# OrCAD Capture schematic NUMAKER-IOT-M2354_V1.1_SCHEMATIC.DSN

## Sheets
1 Nu-Link2-Me: size A3; title: Nu-Link2-Me; rev: 1.0; company: CMHuang; note: Nu-Link2-Me
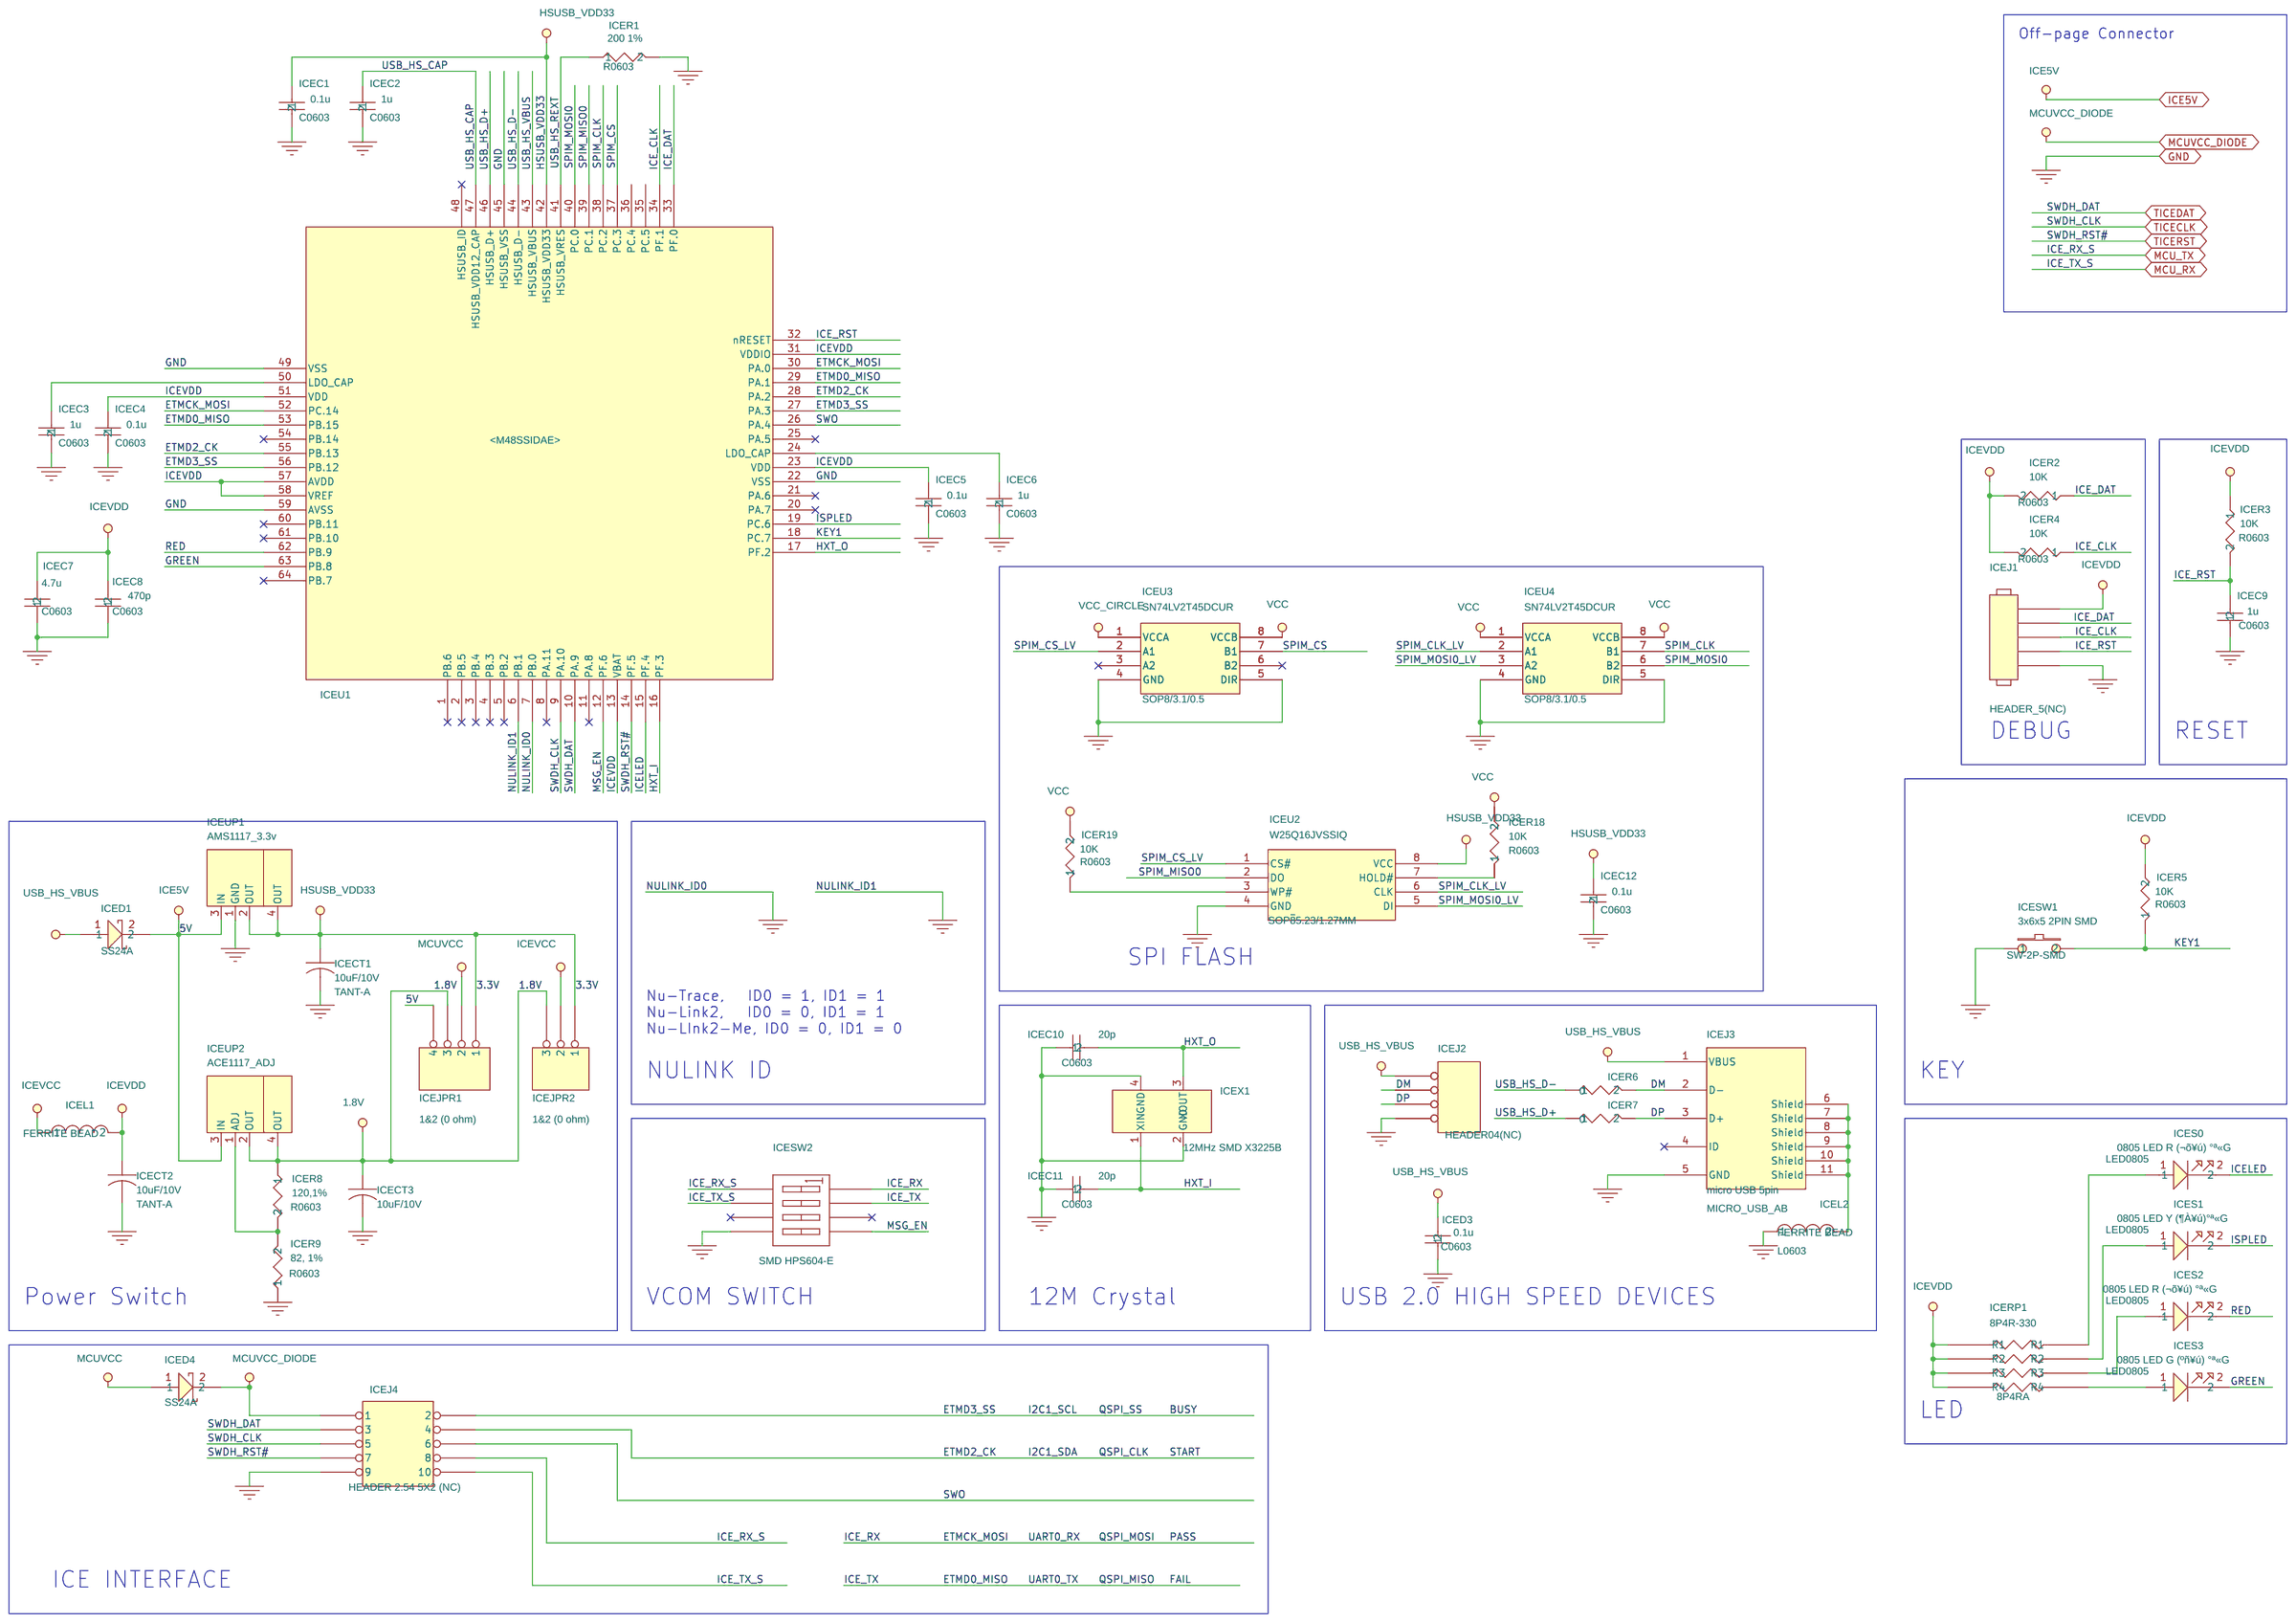
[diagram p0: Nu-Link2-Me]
2 M2354KJFAE: size Custom; title: M2354KJFAE; rev: v1.1; note: NuMaker-IoT-M2354
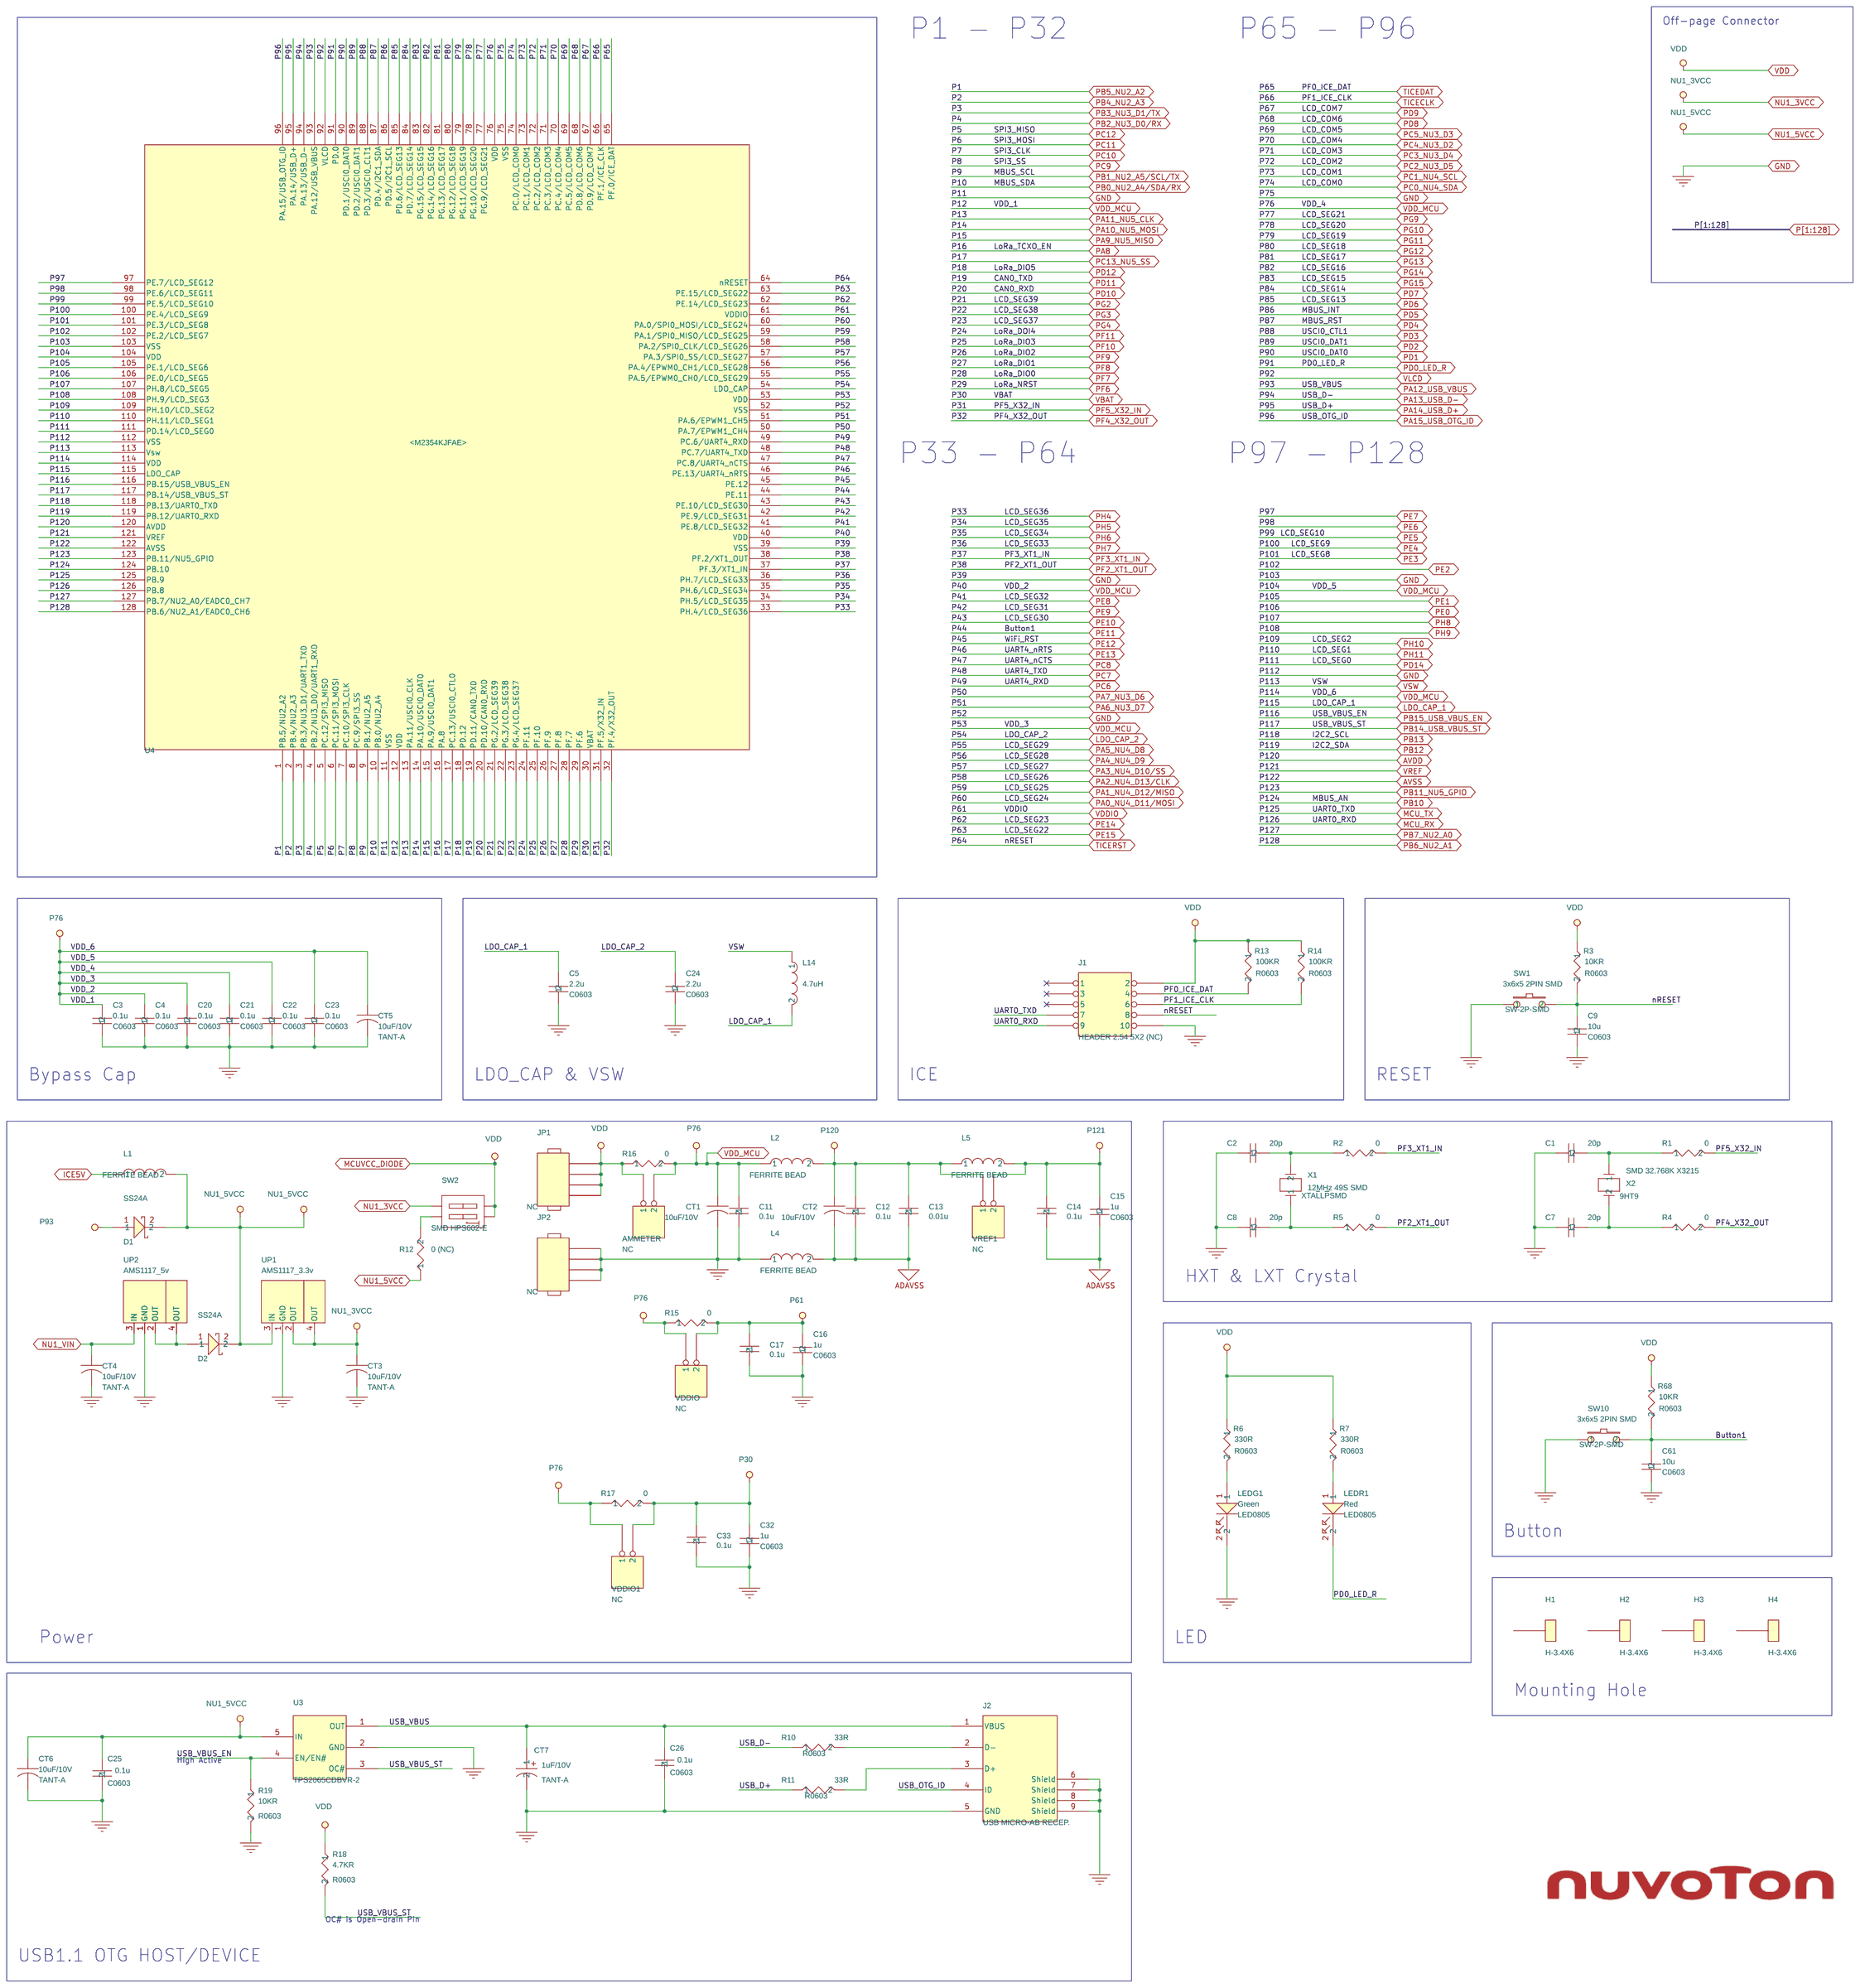
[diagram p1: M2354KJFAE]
3 Ext. Connector: size Custom; title: UNO Interface; rev: v1.1; note: NuMaker-IoT-M2354
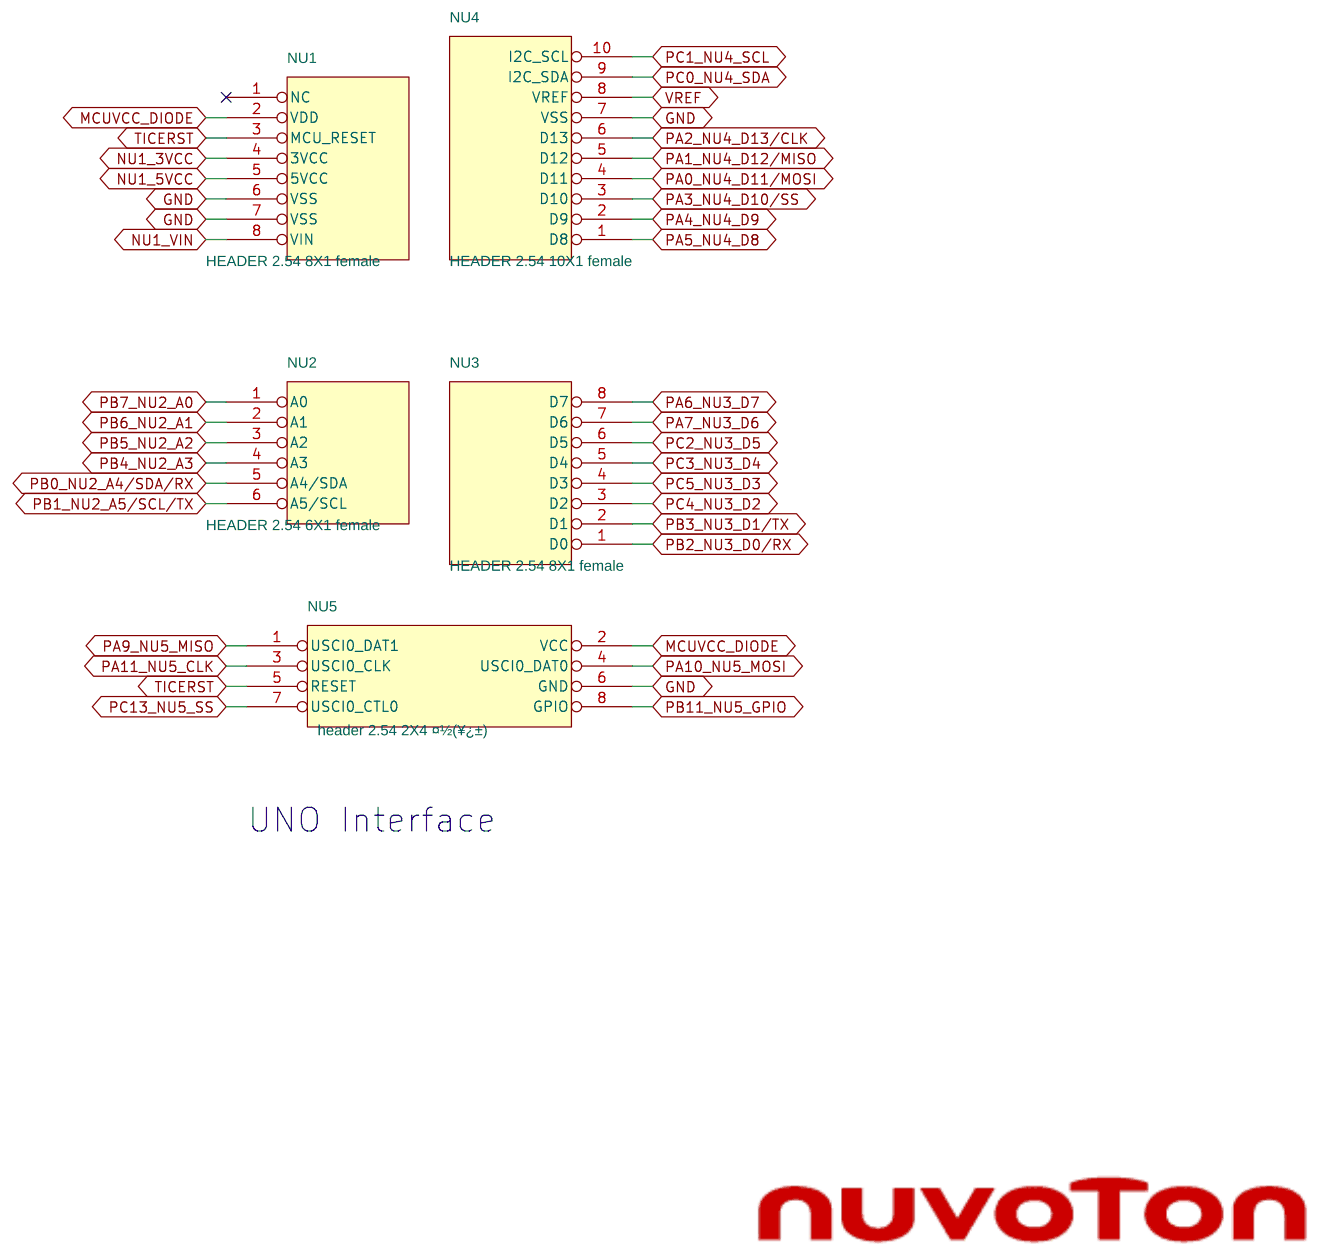
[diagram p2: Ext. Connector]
4 WiFi: size A; title: WiFi; rev: v1.1; note: NuMaker-IoT-M2354
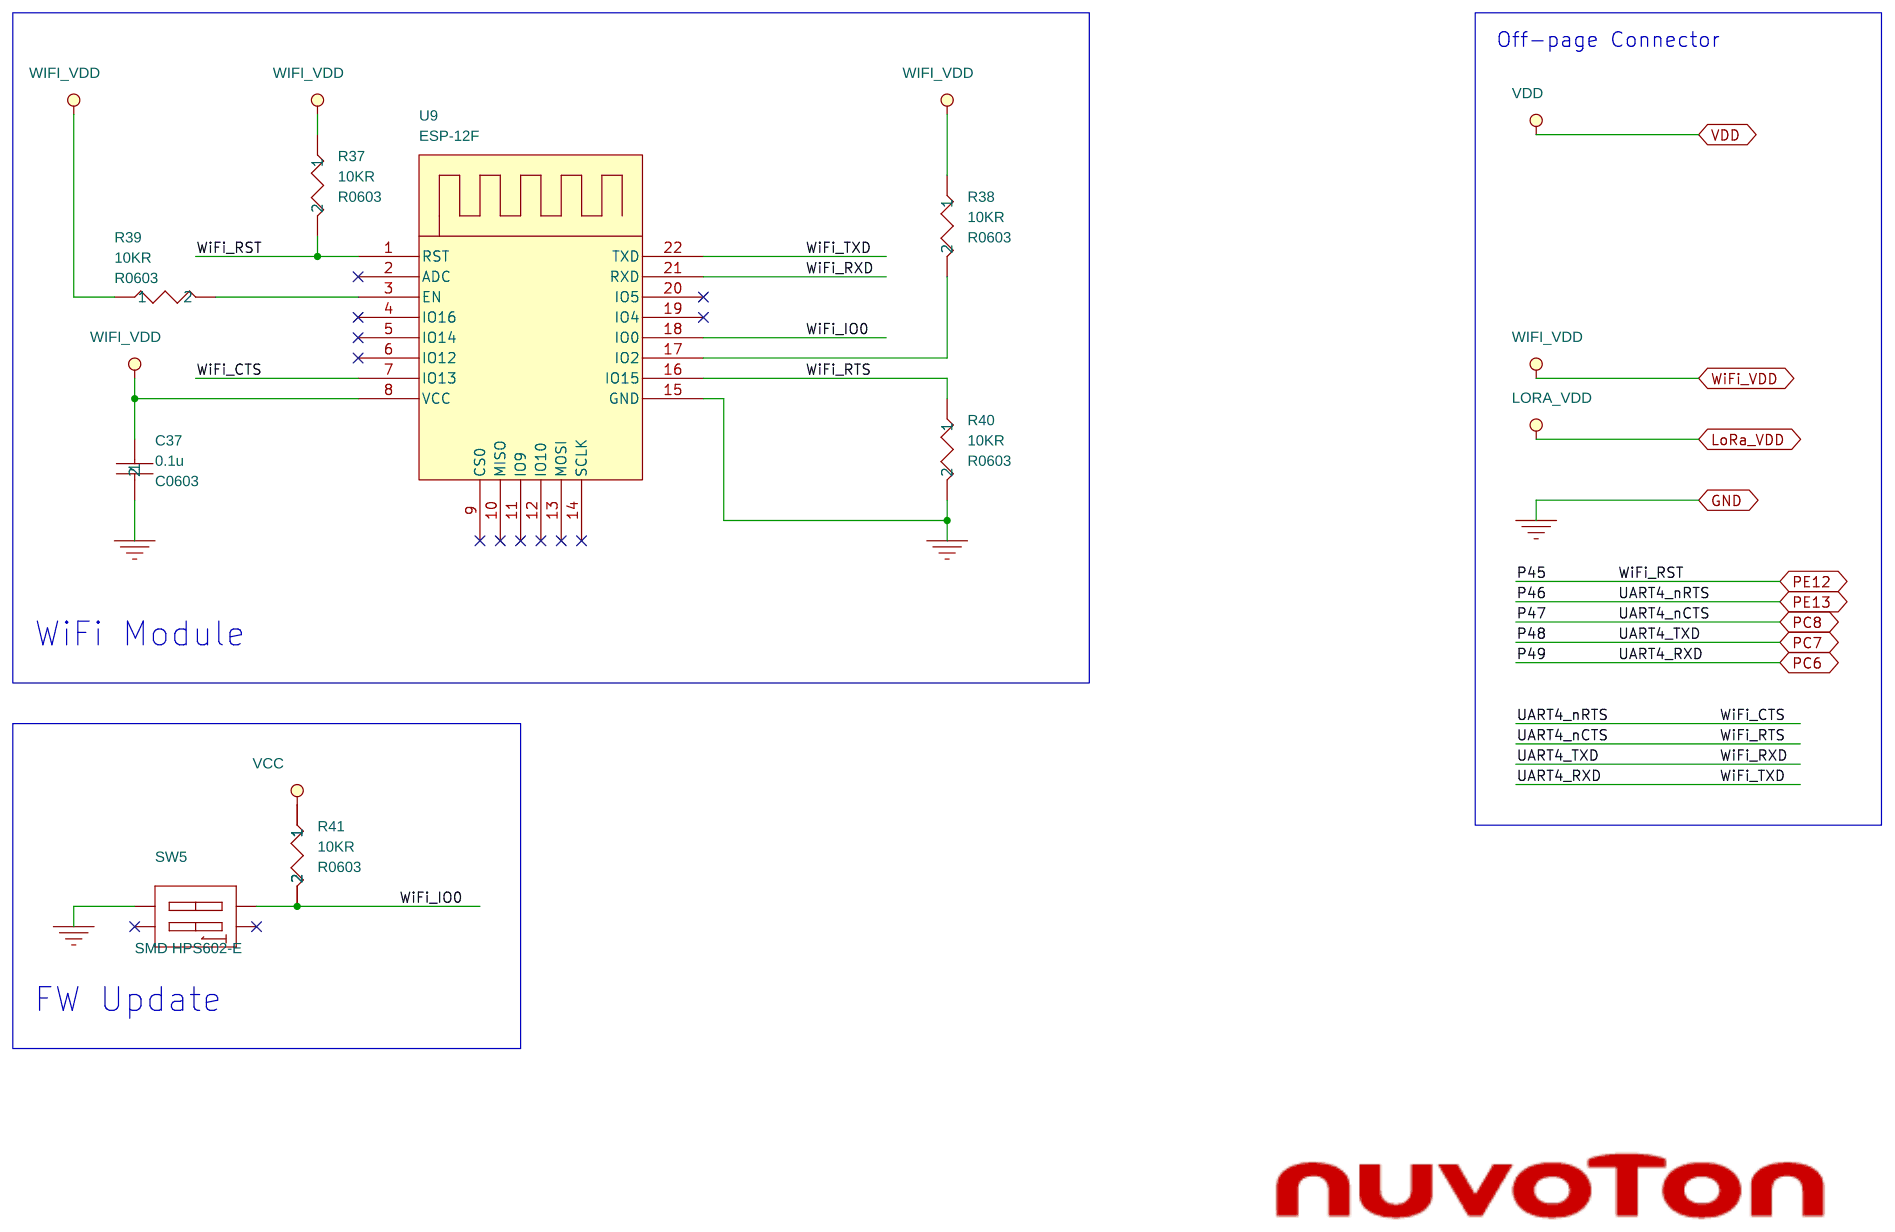
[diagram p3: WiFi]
5 LoRa: size Custom; title: LoRa; rev: v1.1; note: NuMaker-IoT-M2354
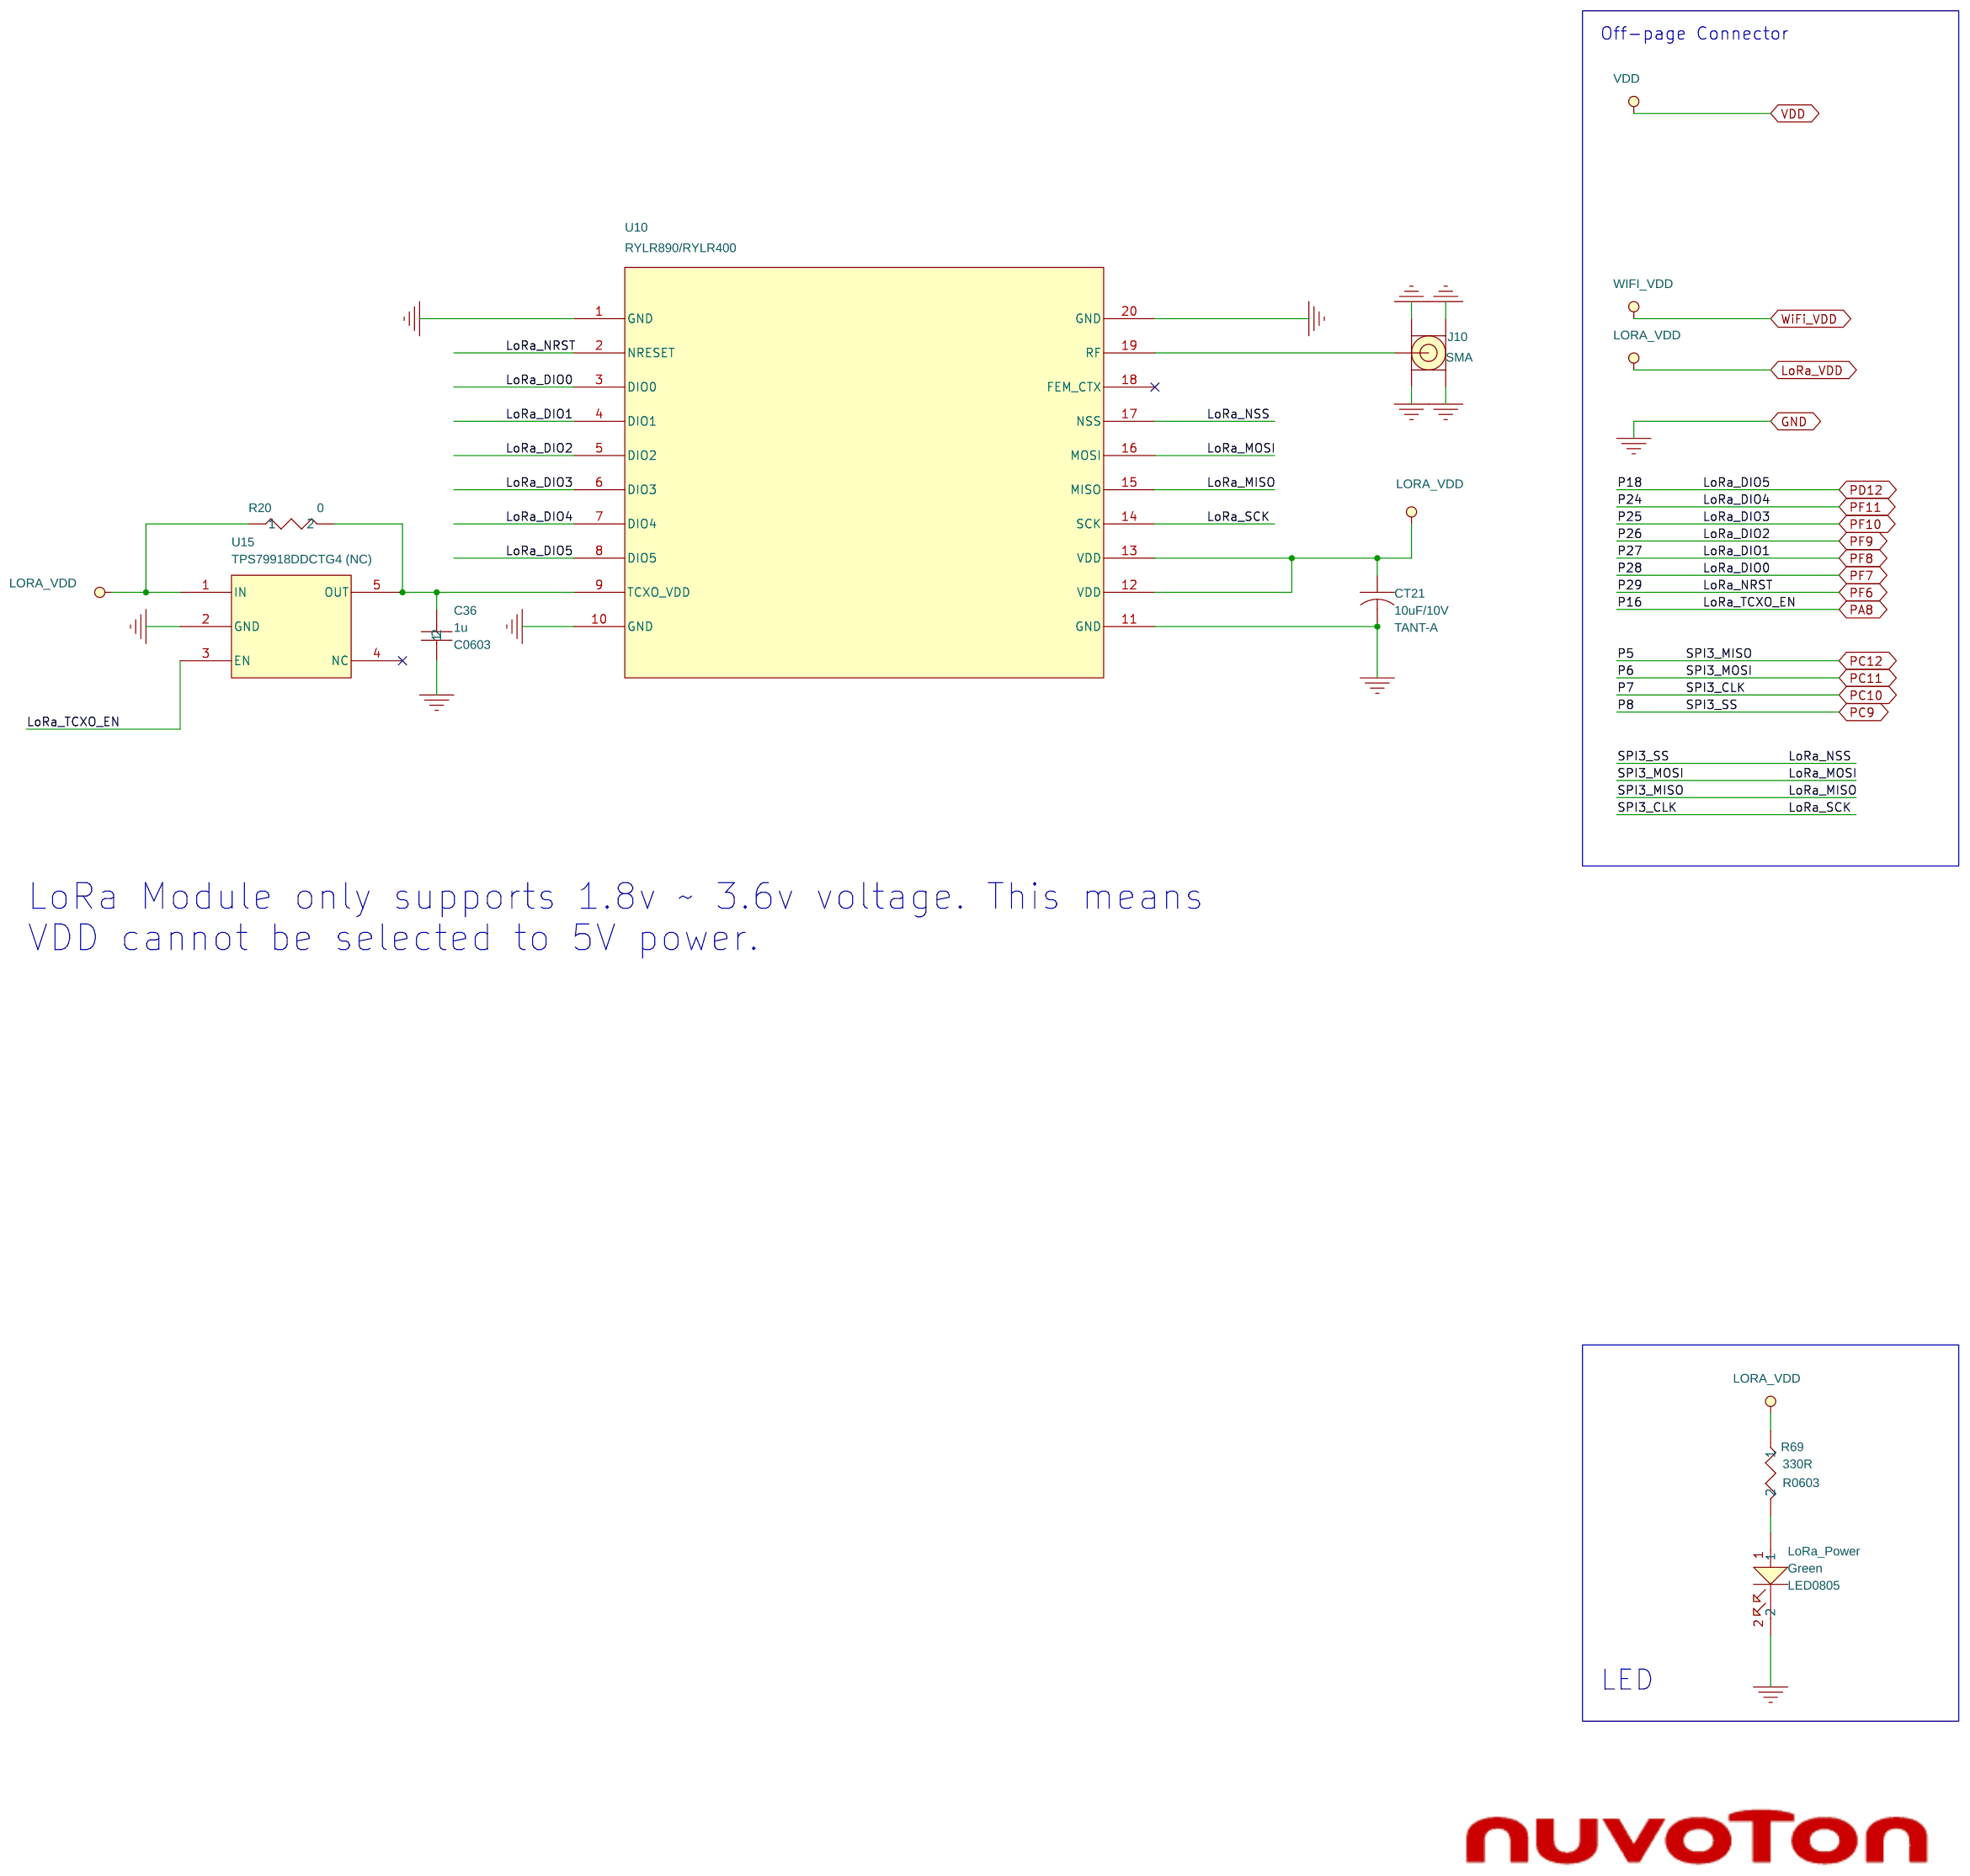
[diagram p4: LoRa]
6 Sensor: size A; title: Sensor; rev: v1.1; note: NuMaker-IoT-M2354
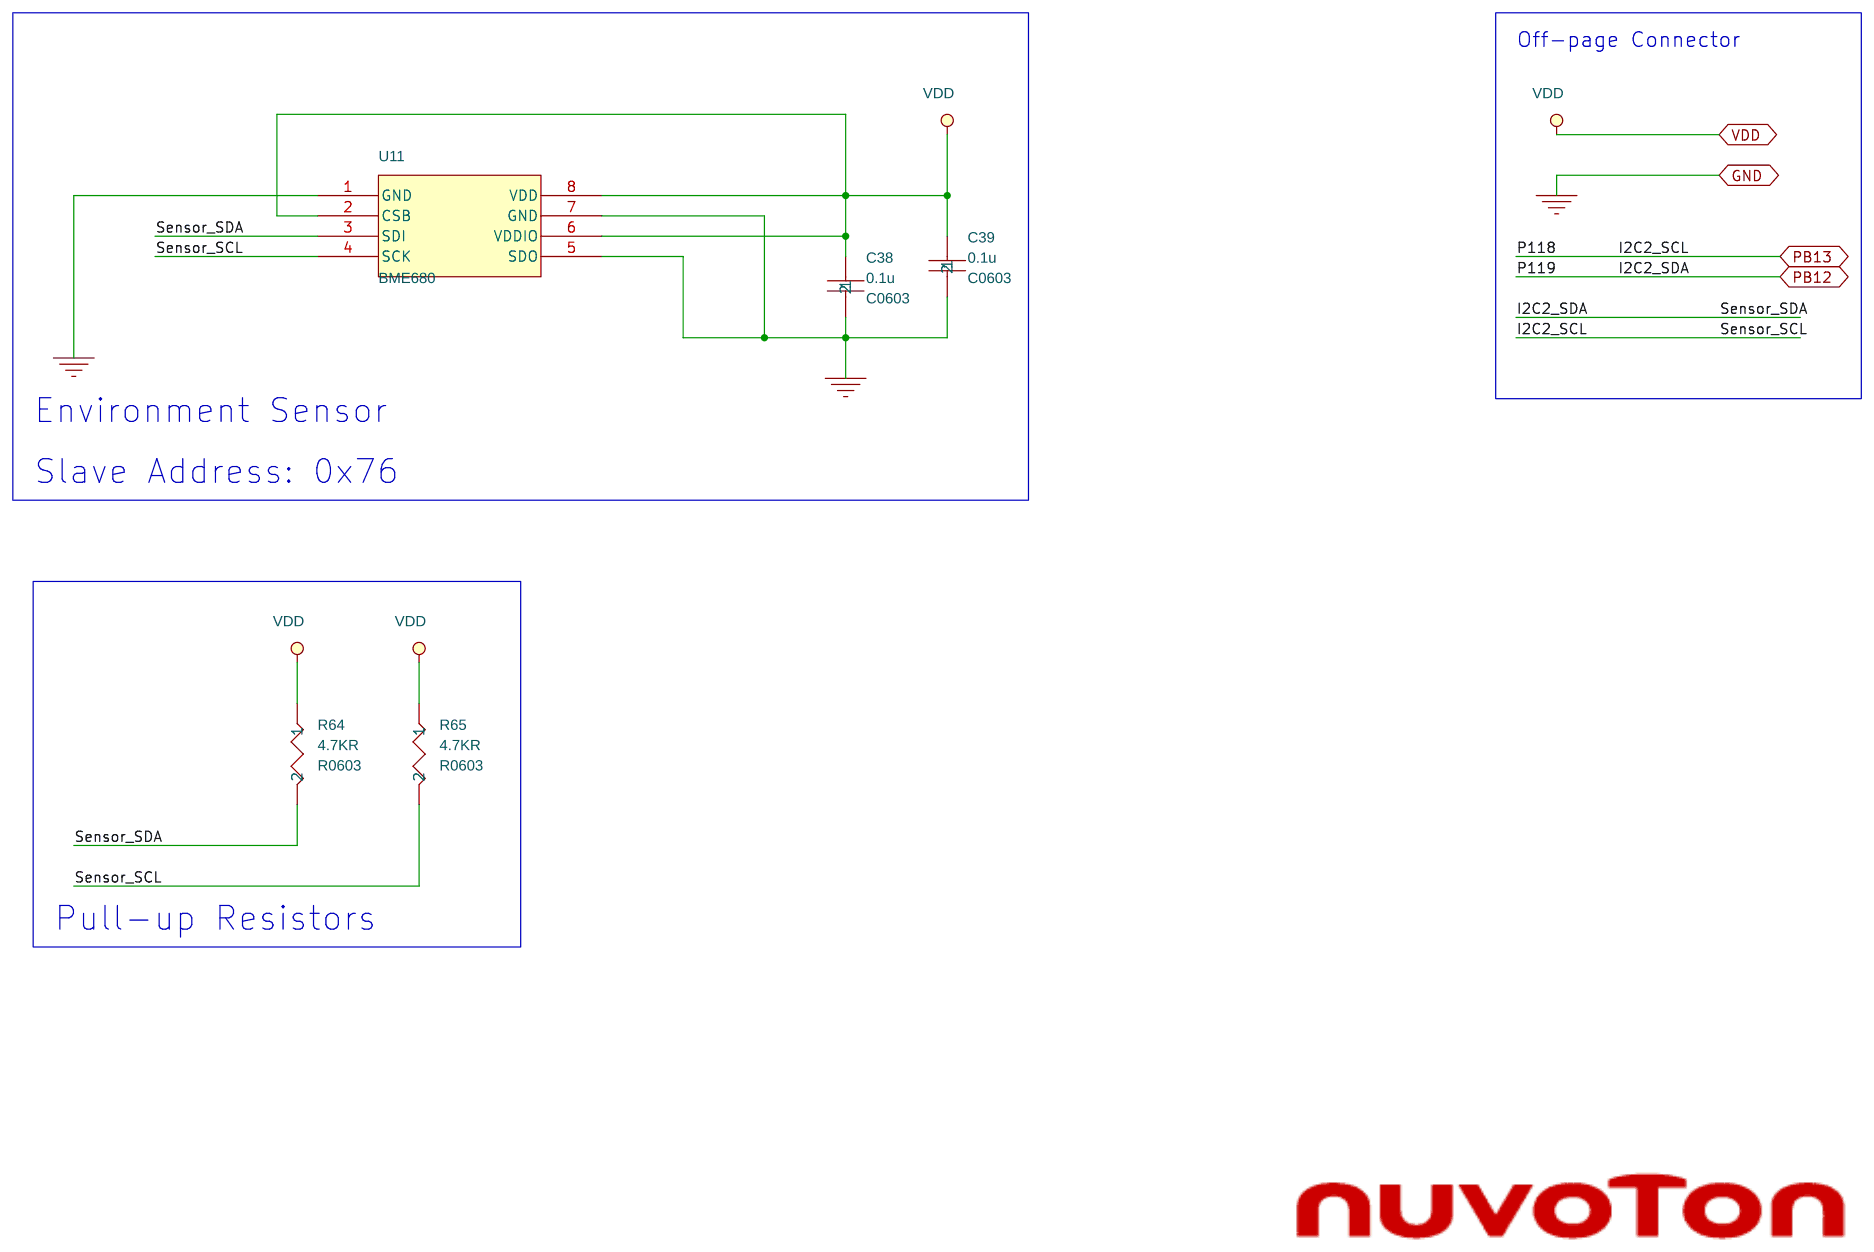
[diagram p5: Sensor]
7 CAN & RS485: size Custom; title: CAN & RS485; rev: v1.1; note: NuMaker-IoT-M2354
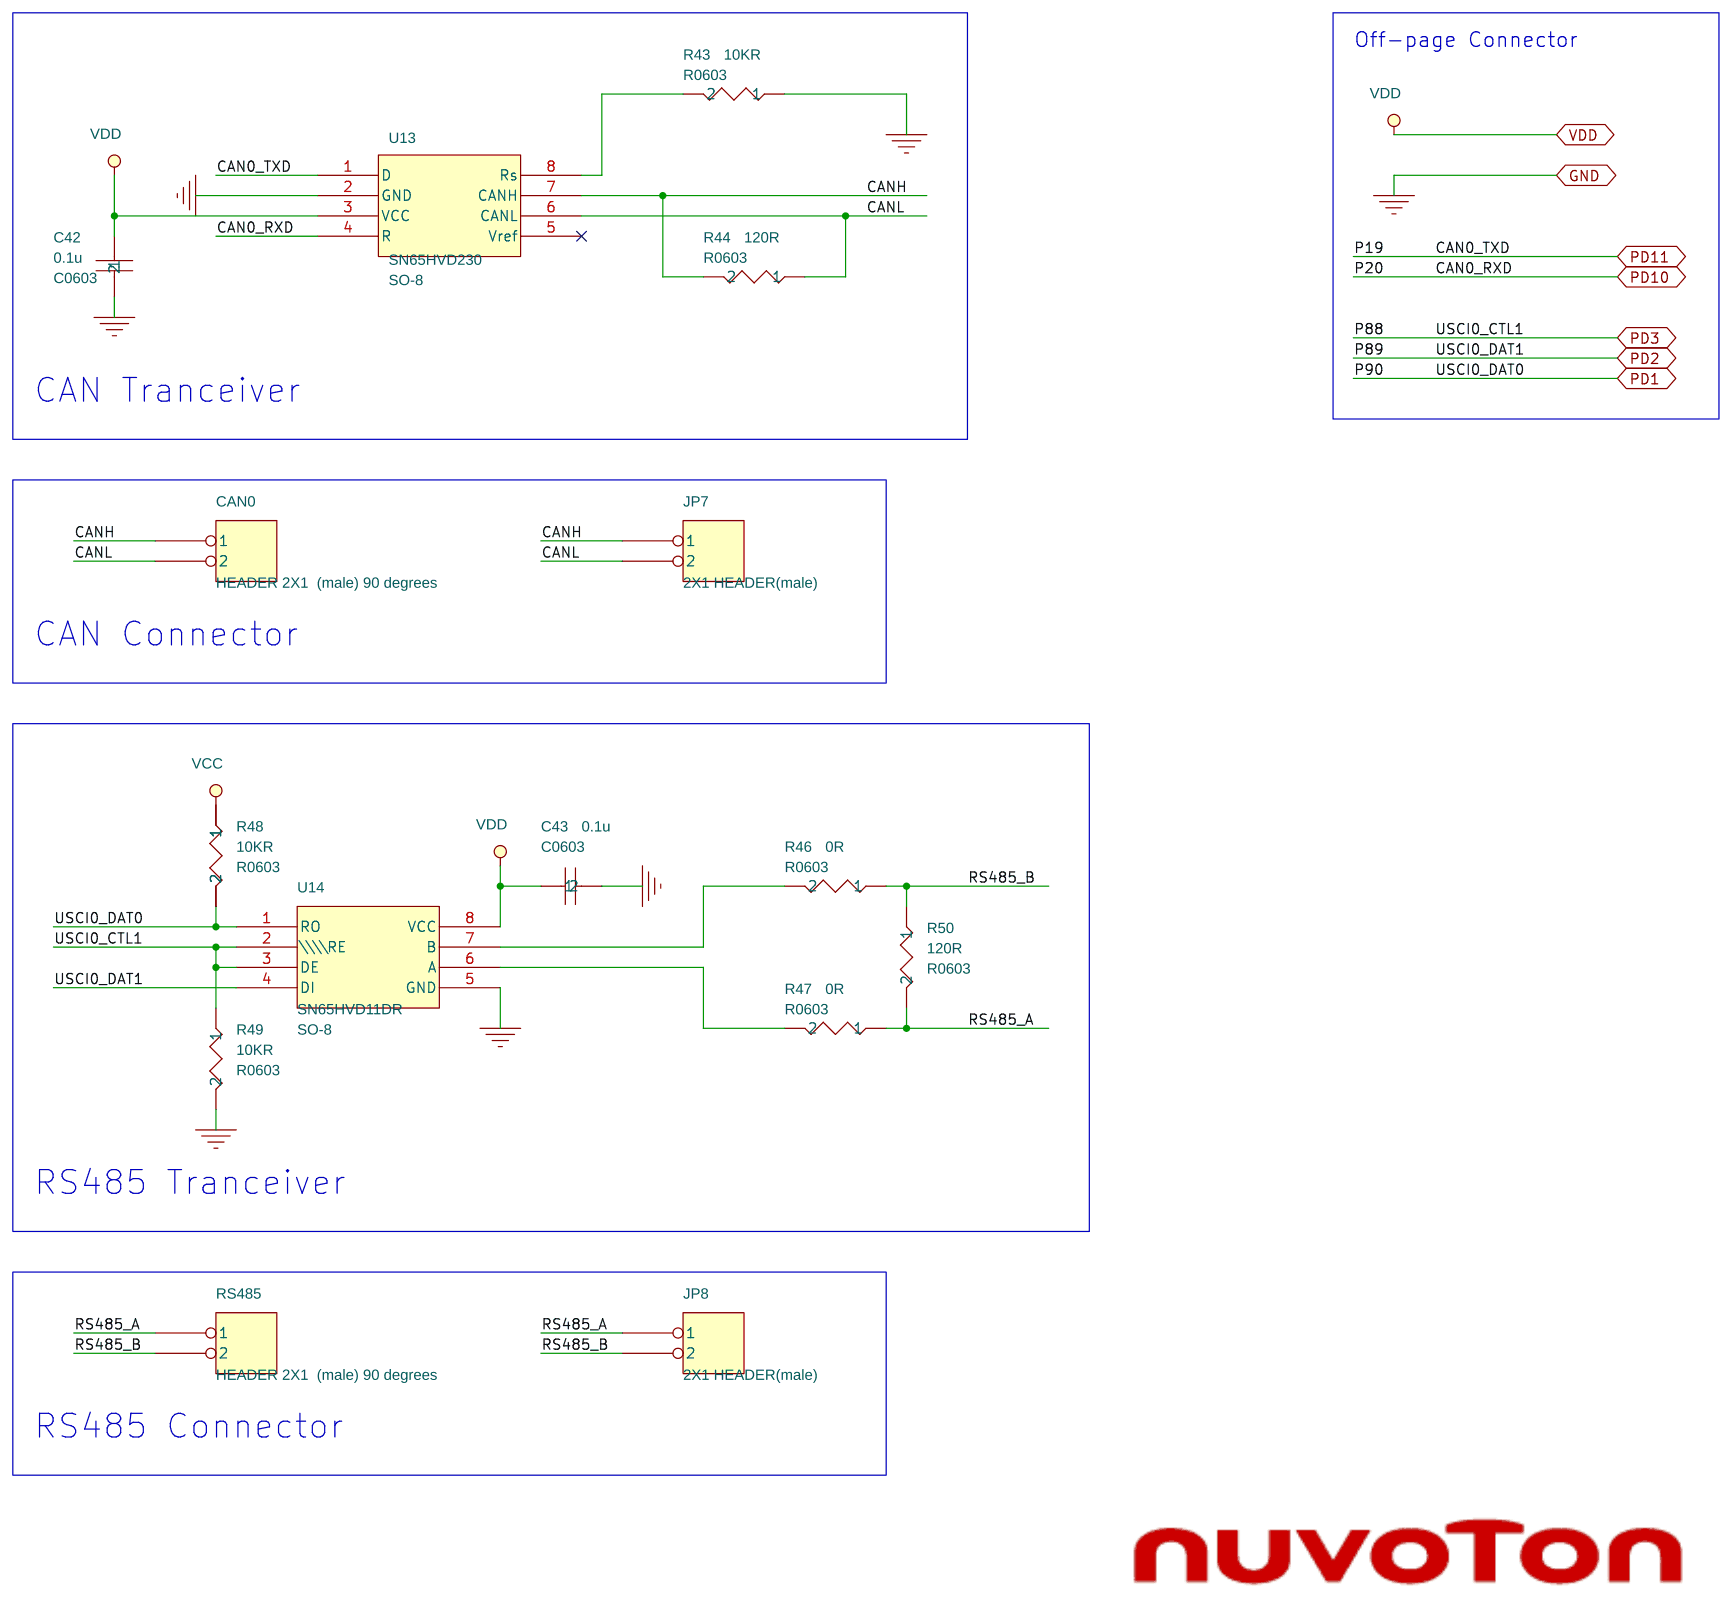
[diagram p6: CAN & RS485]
8 MikroBUS: size A; title: MikroBUS interface; rev: 1.1; note: NuMaker-IoT-M2354
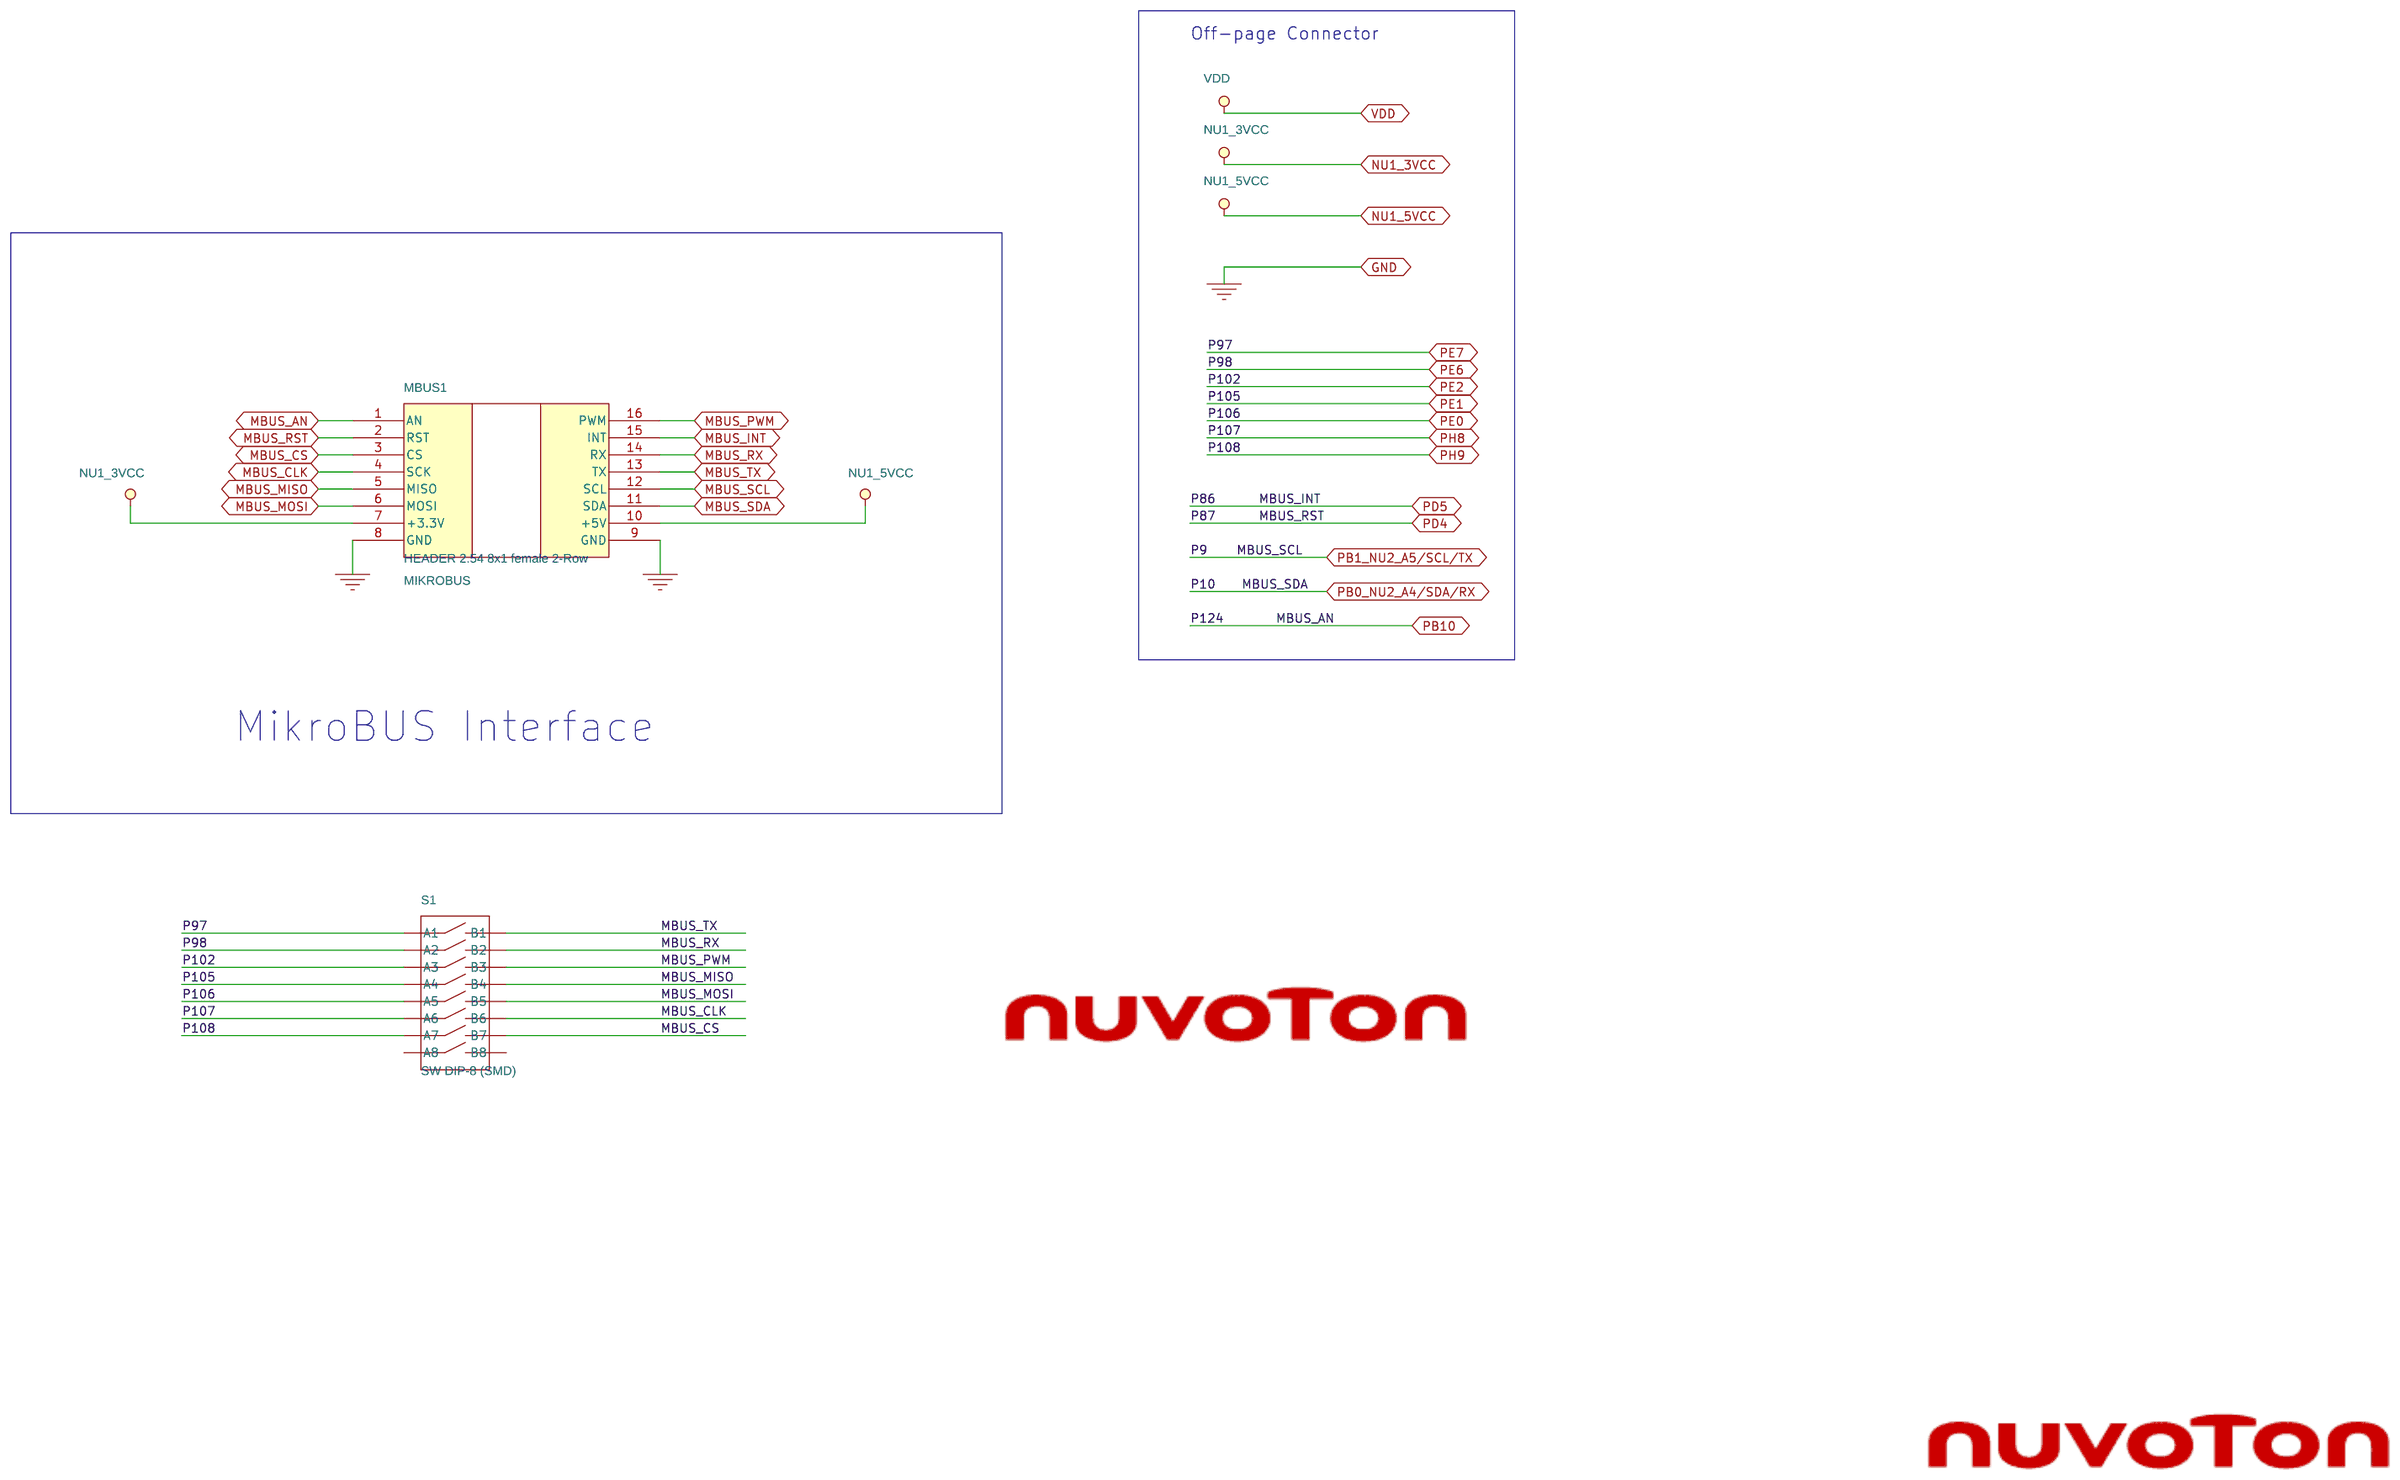
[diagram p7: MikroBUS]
9 LCD: size A; title: LCD interface; rev: V1.1; note: NuMaker-IoT-M2354
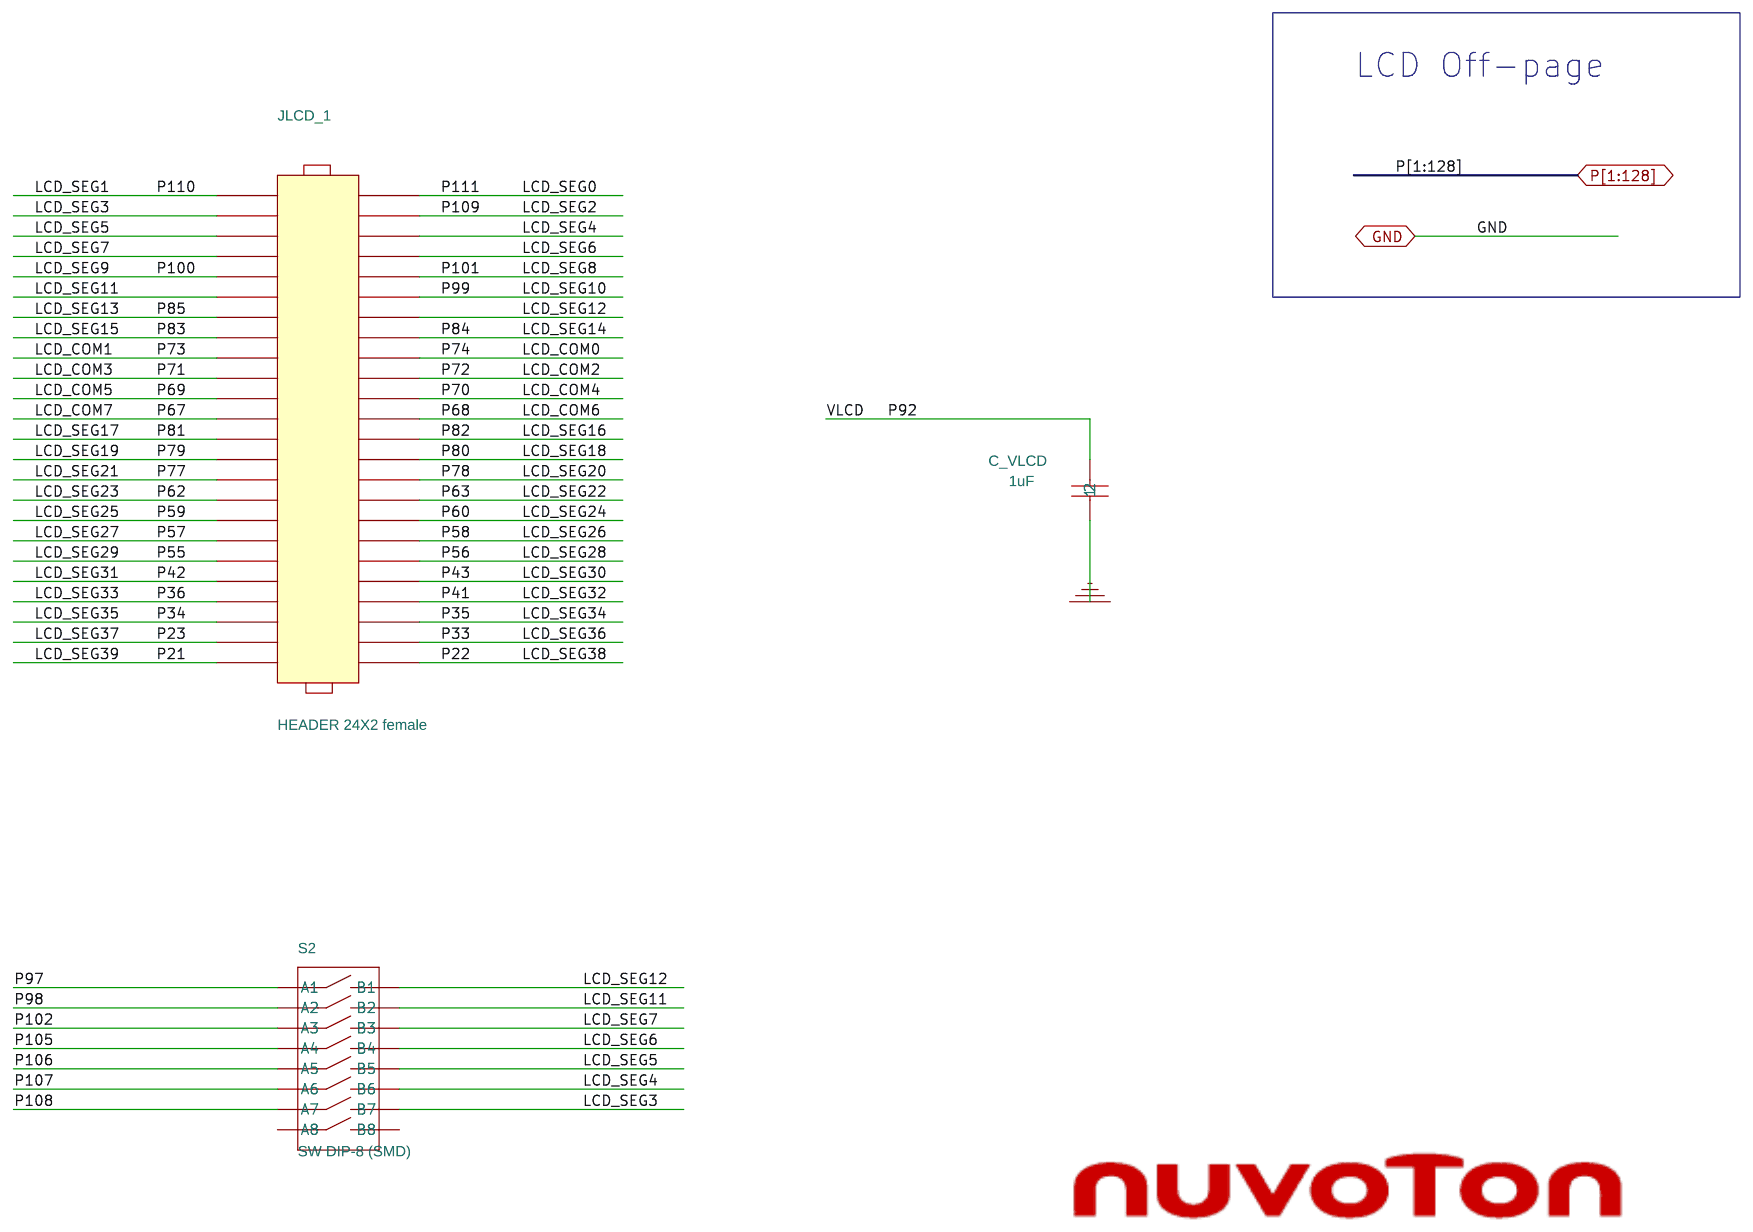
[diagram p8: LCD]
10 Module Power: size Custom; title: Module Power; rev: v1.1; note: NuMaker-IoT-M2354
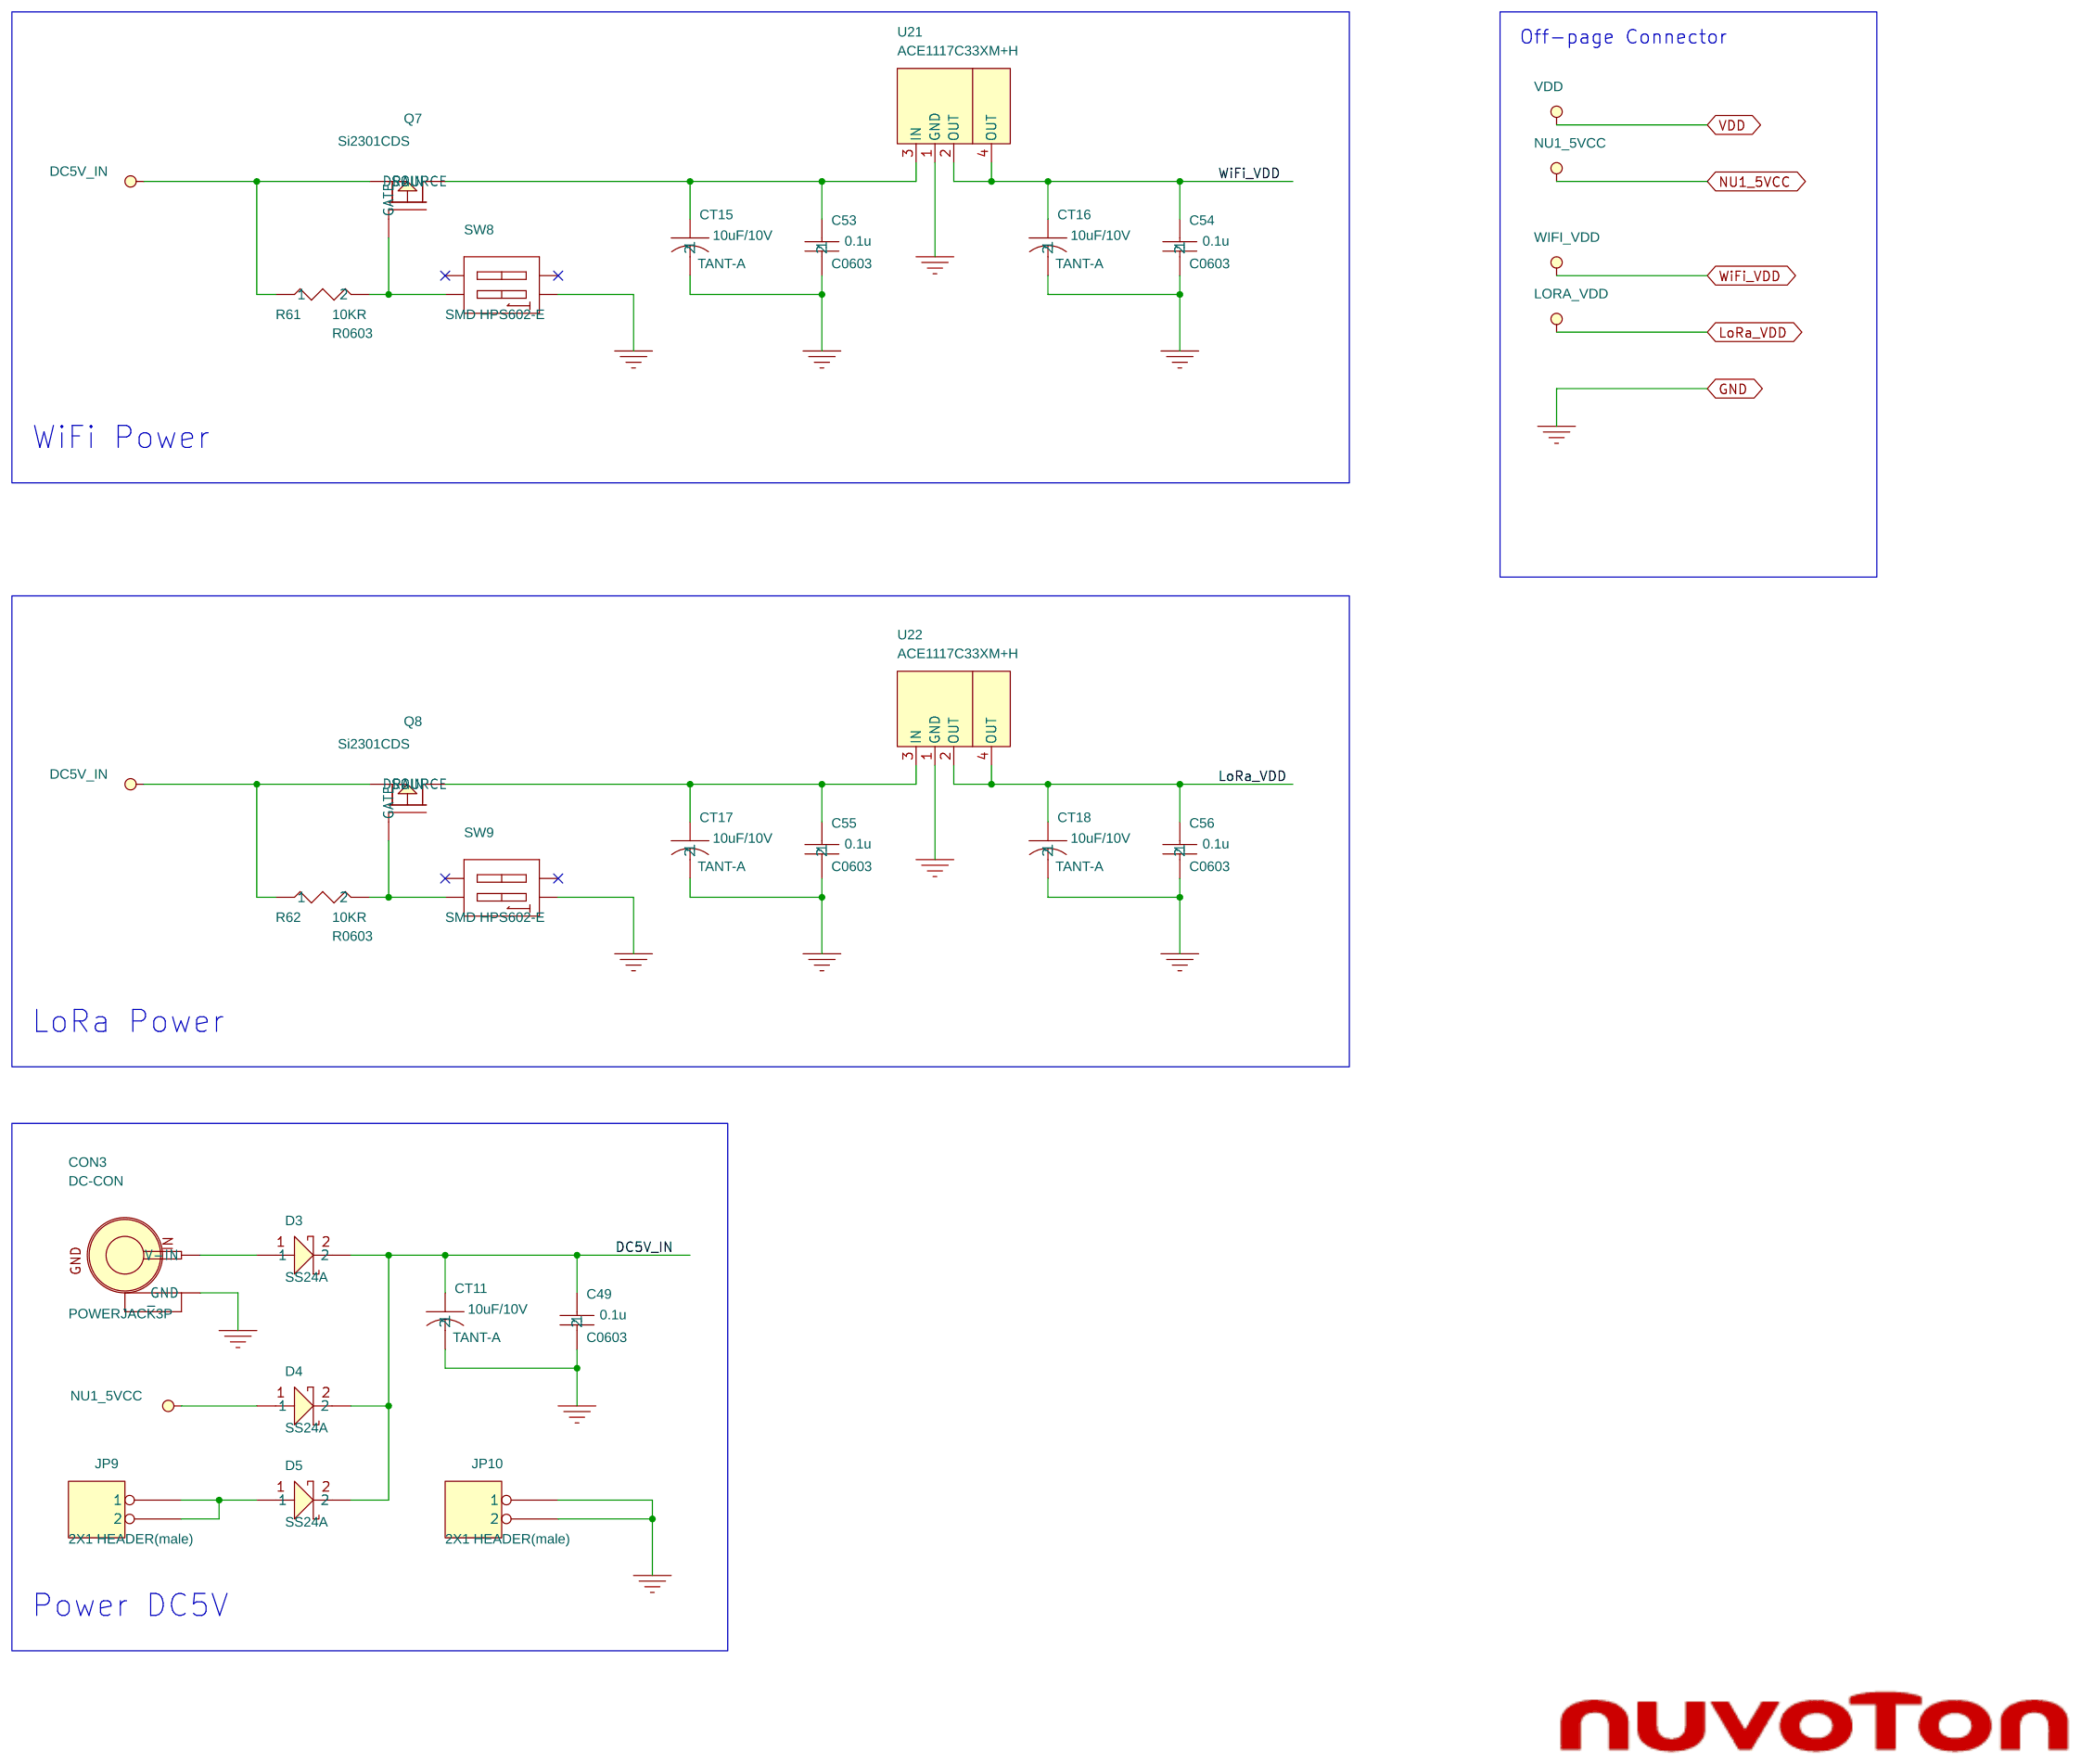
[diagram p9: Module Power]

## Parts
sheet CAN & RS485
C42  0.1u  [C0603]
C43  0.1u  [C0603]
CAN0  HEADER 2X1  (male) 90 degrees  [SIP/2P_3.5MM]
JP7  2X1 HEADER(male)  [HEADER2X1]
JP8  2X1 HEADER(male)  [HEADER2X1]
R43  10KR  [R0603]
R44  120R  [R0603]
R46  0R  [R0603]
R47  0R  [R0603]
R48  10KR  [R0603]
R49  10KR  [R0603]
R50  120R  [R0603]
RS485  HEADER 2X1  (male) 90 degrees  [SIP/2P_3.5MM]
U13  SN65HVD230  [SO-8]
U14  SN65HVD11DR  [SO-8]
sheet Ext. Connector
NU1  HEADER 2.54 8X1 female  [SIP-8P]
NU2  HEADER 2.54 6X1 female  [SIP-6P]
NU3  HEADER 2.54 8X1 female  [SIP-8P]
NU4  HEADER 2.54 10X1 female  [SIP-10P]
NU5  header 2.54 2X4 ¤½(¥¿­±)  [HEADER4X2]
sheet LCD
C_VLCD  1uF  [C0603]
JLCD_1  HEADER 24X2 female  [HEADER24X2_2mm]
S2  SW DIP-8 (SMD)  [SW_DIP-8_(SMD)]
sheet LoRa
C36  1u  [C0603]
CT21  10uF/10V  [TANT-A]
J10  SMA  [SMA_5PIN]
LoRa_Power  Green  [LED0805]
R20  0  [R0603]
R69  330R  [R0603]
U10  RYLR890/RYLR400  [RYLR_LORA]
U15  TPS79918DDCTG4 (NC)  [SOT23-5]
sheet M2354KJFAE
AMMETER  NC  [HEADER2X1]
C1  20p  [C0603]
C2  20p  [C0603]
C3  0.1u  [C0603]
C4  0.1u  [C0603]
C5  2.2u  [C0603]
C7  20p  [C0603]
C8  20p  [C0603]
C9  10u  [C0603]
C11  0.1u  [C0603]
C12  0.1u  [C0603]
C13  0.01u  [C0603]
C14  0.1u  [C0603]
C15  1u  [C0603]
C16  1u  [C0603]
C17  0.1u  [C0603]
C20  0.1u  [C0603]
C21  0.1u  [C0603]
C22  0.1u  [C0603]
C23  0.1u  [C0603]
C24  2.2u  [C0603]
C25  0.1u  [C0603]
C26  0.1u  [C0603]
C32  1u  [C0603]
C33  0.1u  [C0603]
C61  10u  [C0603]
CT1  10uF/10V  [TANT-A]
CT2  10uF/10V  [TANT-A]
CT3  10uF/10V  [TANT-A]
CT4  10uF/10V  [TANT-A]
CT5  10uF/10V  [TANT-A]
CT6  10uF/10V  [TANT-A]
CT7  1uF/10V  [TANT-A]
D1  SS24A  [RB060L]
D2  SS24A  [RB060L]
H1  H-3.4X6  [H-3.4X6]
H2  H-3.4X6  [H-3.4X6]
H3  H-3.4X6  [H-3.4X6]
H4  H-3.4X6  [H-3.4X6]
J1  HEADER 2.54 5X2 (NC)  [HEADER5X2]
J2  USB MICRO-AB RECEP.  [MICRO_USB_AB_LS]
JP1  NC  [header1x4]
JP2  NC  [header1x4]
L1  FERRITE BEAD  [L0603]
L2  FERRITE BEAD  [L0603]
L4  FERRITE BEAD  [L0603]
L5  FERRITE BEAD  [L0603]
L14  4.7uH  [L-VLF403215MT]
LEDG1  Green  [LED0805]
LEDR1  Red  [LED0805]
R1  0  [R0603]
R2  0  [R0603]
R3  10KR  [R0603]
R4  0  [R0603]
R5  0  [R0603]
R6  330R  [R0603]
R7  330R  [R0603]
R10  33R  [R0603]
R11  33R  [R0603]
R12  0 (NC)  [R0603]
R13  100KR  [R0603]
R14  100KR  [R0603]
R15  0  [R0603]
R16  0  [R0603]
R17  0  [R0603]
R18  4.7KR  [R0603]
R19  10KR  [R0603]
R68  10KR  [R0603]
SW1  3x6x5 2PIN SMD  [SW-2P-SMD]
SW2  SMD HPS602-E  [SW1X2]
SW10  3x6x5 2PIN SMD  [SW-2P-SMD]
U3  TPS2065CDBVR-2  [SOT23-5]
U4  M2354KJFAE  [MCU_LQFP_128]
UP1  AMS1117_3.3v  [SOT-223-1]
UP2  AMS1117_5v  [SOT-223-1]
VDDIO  NC  [HEADER2X1]
VDDIO1  NC  [HEADER2X1]
VREF1  NC  [HEADER2X1]
X1  12MHz 49S SMD  [XTAL\LP\SMD]
X2  SMD 32.768K X3215  [9HT9]
sheet MikroBUS
MBUS1  HEADER 2.54 8x1 female 2-Row  [MIKROBUS]
S1  SW DIP-8 (SMD)  [SW_DIP-8_(SMD)]
sheet Module Power
C49  0.1u  [C0603]
C53  0.1u  [C0603]
C54  0.1u  [C0603]
C55  0.1u  [C0603]
C56  0.1u  [C0603]
CON3  DC-CON  [POWERJACK\3P]
CT11  10uF/10V  [TANT-A]
CT15  10uF/10V  [TANT-A]
CT16  10uF/10V  [TANT-A]
CT17  10uF/10V  [TANT-A]
CT18  10uF/10V  [TANT-A]
D3  SS24A  [RB060L]
D4  SS24A  [RB060L]
D5  SS24A  [RB060L]
JP9  2X1 HEADER(male)  [HEADER2X1]
JP10  2X1 HEADER(male)  [HEADER2X1]
Q7  Si2301CDS  [SOT-23]
Q8  Si2301CDS  [SOT-23]
R61  10KR  [R0603]
R62  10KR  [R0603]
SW8  SMD HPS602-E  [SW1X2]
SW9  SMD HPS602-E  [SW1X2]
U21  ACE1117C33XM+H  [SOT-223-1]
U22  ACE1117C33XM+H  [SOT-223-1]
sheet Nu-Link2-Me
ICEC1  0.1u  [C0603]
ICEC2  1u  [C0603]
ICEC3  1u  [C0603]
ICEC4  0.1u  [C0603]
ICEC5  0.1u  [C0603]
ICEC6  1u  [C0603]
ICEC7  4.7u  [C0603]
ICEC8  470p  [C0603]
ICEC9  1u  [C0603]
ICEC10  20p  [C0603]
ICEC11  20p  [C0603]
ICEC12  0.1u  [C0603]
ICECT1  10uF/10V  [TANT-A]
ICECT2  10uF/10V  [TANT-A]
ICECT3  10uF/10V  [TANT-A]
ICED1  SS24A  [RB060L]
ICED3  0.1u  [C0603]
ICED4  SS24A  [RB060L]
ICEJ1  HEADER_5(NC)  [HEADER5X1]
ICEJ2  HEADER04(NC)  [HEADER04]
ICEJ3  micro USB 5pin  [MICRO_USB_AB]
ICEJ4  HEADER 2.54 5X2 (NC)  [HEADER5X2]
ICEJPR1  1&2 (0 ohm)  [R0603X3]
ICEJPR2  1&2 (0 ohm)  [R0603X2]
ICEL1  FERRITE BEAD  [L0603]
ICEL2  FERRITE BEAD  [L0603]
ICER1  200 1%  [R0603]
ICER2  10K  [R0603]
ICER3  10K  [R0603]
ICER4  10K  [R0603]
ICER5  10K  [R0603]
ICER6  0  [R0603]
ICER7  0  [R0603]
ICER8  120,1%  [R0603]
ICER9  82, 1%  [R0603]
ICER18  10K  [R0603]
ICER19  10K  [R0603]
ICERP1  8P4R-330  [8P4RA]
ICES0  0805 LED R (¬õ¥ú) °ª«G  [LED0805]
ICES1  0805 LED Y (¶À¥ú)°ª«G  [LED0805]
ICES2  0805 LED R (¬õ¥ú) °ª«G  [LED0805]
ICES3  0805 LED G (ºñ¥ú) °ª«G  [LED0805]
ICESW1  3x6x5 2PIN SMD  [SW-2P-SMD]
ICESW2  SMD HPS604-E  [SW1X4]
ICEU1  M48SSIDAE  [LQFP64_7x7_M48SSIDAE]
ICEU2  W25Q16JVSSIQ  [SOP8\5.23/1.27MM]
ICEU3  SN74LV2T45DCUR  [SOP8/3.1/0.5]
ICEU4  SN74LV2T45DCUR  [SOP8/3.1/0.5]
ICEUP1  AMS1117_3.3v  [SOT-223-1]
ICEUP2  ACE1117_ADJ  [SOT-223-1]
ICEX1  12MHz SMD X3225B  [CRYSTAL_SMD]
sheet Sensor
C38  0.1u  [C0603]
C39  0.1u  [C0603]
R64  4.7KR  [R0603]
R65  4.7KR  [R0603]
U11  BME680  [QFN8/3X3/0.8MM]
sheet WiFi
C37  0.1u  [C0603]
R37  10KR  [R0603]
R38  10KR  [R0603]
R39  10KR  [R0603]
R40  10KR  [R0603]
R41  10KR  [R0603]
SW5  SMD HPS602-E  [SW1X2]
U9  ESP-12F  [ESP-12F_MODULE]

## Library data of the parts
C38 C42 = C_0.1u_1
C37 C39 C43 = C_0.1u
CAN0 JP9 VREF1 = HEADER_2
JP7 VDDIO1 = HEADER_2_3
AMMETER JP8 JP10 = HEADER_2_1
ICER9 R43 = R_0_3: Package: 0603
ICER2 R7 R44 = R_0_2: Package: 0603
ICER18 R46 R61 = R_0: Package: 0603
ICER19 R47 R62 R69 = R_0_1: Package: 0603
R40 R48 R64 = R_100_1
R39 R49 R65 = R_100
R38 R50 = R_100_2
RS485 VDDIO = HEADER_2_2
U13 = SN65HVD230
U14 = ADM232_0: Package: DIP16\SO
NU1 = POWER_CONNECT_0
NU2 = ADC_CONNECT_0
NU3 = PWM0_CONNECT_0
NU4 = PWM1_CONNECT_1
NU5 = NuEdu_NU7_0
C_VLCD = CAP-C: Package: 0603
JLCD_1 = HEADER_24X2
S1 S2 = SW_DIP-8
C36 ICEC6 = CAP-C: Package: 0603; element_no: C0006
CT1-CT6 CT21 ICECT1-ICECT3 = C_10uF_10V
J10 = CON-SMA_2
ICES0 LEDR1 LoRa_Power = LED_0: Package: KP-2012; Vendor: Kingbright
R16 R20 = R_0
U10 = RYB050I_36
U15 = AT26DF081A_0
C1 = C_20p_3
C2 = C_20p
C3 ICED3 = CAP-C_2: Package: 0603; element_no: C0004
C4 ICEC5 = CAP-C_10: Package: 0603; element_no: C0004
C5 ICEC9 = CAP-C_4: Package: 0603; element_no: C0006
C7 = C_20p_1
C8 = C_20p_2
C9 = CAP-C_11: Package: 0603; element_no: C0006
C11 = C_0.1u: element_no: C0004
C12 = C_0.1u_2: element_no: C0004
C13 = C_0.1u_4: element_no: C0003
C14 = C_0.1u_1: element_no: C0004
C15 = CAP-C_5: Package: 0603; element_no: C0006
C16 = CAP-C_12: Package: 0603; element_no: C0006
C17 = C_0.1u_3: element_no: C0004
C20 ICEC1 = CAP-C_1: Package: 0603; element_no: C0004
C21 = CAP-C: Package: 0603; element_no: C0004
C22 = CAP-C_8: Package: 0603; element_no: C0004
C23 = CAP-C_3: Package: 0603; element_no: C0004
C24 = CAP-C_7: Package: 0603; element_no: C0006
C25 C56 = CAP-B: Package: 0603
C26 C49 = CAP-B_1: Package: 0603
C32 ICEC3 = CAP-C_6: Package: 0603; element_no: C0006
C33 = C_0.1u_5: element_no: C0004
C61 = CAP-C_9: Package: 0603; element_no: C0006
CT7 = CAP-T: Package: TANT-R
D1 D3 ICED4 = D_SS24A_1
D2 D5 ICED1 = D_SS24A
H1-H4 = TEST_POINT
ICEJ4 J1 = HEADER_5X2
J2 = USB_type_B_mini_connector
JP1 JP2 = HEADER_4_v2
L1 = FERRITE_BEAD_3
L2 = FERRITE_BEAD_2
ICEL2 L4 = FERRITE_BEAD_1
ICEL1 L5 = FERRITE_BEAD
L14 = INDUCTOR
ICES3 LEDG1 = LED_0_1: Package: KP-2012; Vendor: Kingbright
R1 = R_0_1
R2 = R_0_4
ICER4 R3 = R_0_5: Package: 0603
R4 = R_0_17
R5 = R_0_3
R6 = R_0_11: Package: 0603
R10 = R_0_9: Package: 0603
R11 = R_0_16: Package: 0603
R12 = R_0_12
R13 = R_0_10: Package: 0603
R14 = R_0_13: Package: 0603
R15 = R_0_7
R17 = R_0_14
ICER8 R18 = R_0_6: Package: 0603
R19 = R_0_15: Package: 0603
ICER1 R68 = R_0_8: Package: 0603
SW1 = SW_PUSHBUTTON_0_1
SW2 SW5 SW8 SW9 = SW_DIP-4_2
ICESW1 SW10 = SW_PUSHBUTTON_0
U3 = NCT3520U
U4 = M263KIAAE_2: M263KIAAE: <M2354KJFAE>
ICEUP1 U21 U22 UP1 UP2 = TO-247_Regulator_10
X1 = Xtal_12MHz
X2 = Xtal_32.768K
MBUS1 = MikroBUS_2
C53 = CAP-B_2: Package: 0603
C54 = CAP-B_3: Package: 0603
C55 = CAP-B_4: Package: 0603
CON3 = DC-CON
CT11 = CAP_4: Package: TANT-R
CT15 = CAP: Package: TANT-R
CT16 = CAP_1: Package: TANT-R
CT17 = CAP_3: Package: TANT-R
CT18 = CAP_2: Package: TANT-R
D4 = D_SS24A_2
Q7 Q8 = Si2301BDS_P-FET_5
ICEC2 = CAP-C_8: Package: 0603; element_no: C0006
ICEC4 = CAP-C_5: Package: 0603; element_no: C0004
ICEC7 = CAP-C_3: Package: 0603
ICEC8 = CAP-C_9: Package: 0603
ICEC10 = CAP-C_12: Package: 0603
ICEC11 = CAP-C_11: Package: 0603
ICEC12 = CAP-C_7: Package: 0603; element_no: C0004
ICEJ1 = HEADER_5
ICEJ2 = HEADER_4
ICEJ3 = micro_USB_5pin_0
ICEJPR1 = HEADER_3_0
ICEJPR2 = HEADER_3
ICER3 = R_0_4: Package: 0603
ICER5 = R_0_7: Package: 0603
ICER6 = R_33
ICER7 = R_33_1
ICERP1 = R-PACK8_0
ICES1 = LED_0_3: Package: KP-2012; Vendor: Kingbright
ICES2 = LED_0_2: Package: KP-2012; Vendor: Kingbright
ICESW2 = SW_DIP-4_SM
ICEU1 = M487SIDAE_0: M487SIDAE: <M48SSIDAE>
ICEU2 = W25P10_20_40_SOIC_0: Package: SOP8; Vendor: WINBOND
ICEU3 ICEU4 = SN74LV2T45
ICEUP2 = TO-247_Regulator_0
ICEX1 = Crystal_SMD_1
U11 = BME680
R37 = R_100_3
R41 = R_100_4
U9 = ESP-12

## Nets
1.8V: ICECT3.1 ICEJPR1.3 ICEJPR2.3 ICER8.1 ICEUP2.2(OUT) ICEUP2.4(OUT)
3.3V: ICEC1.1 ICEC12.1 ICECT1.1 ICEJPR1.1 ICEJPR2.1 ICER18.2 ICER19.2 ICEU1.42(HSUSB_VDD33) ICEU2.8(VCC) ICEU3.1(VCCA) ICEU4.1(VCCA) ICEUP1.2(OUT) ICEUP1.4(OUT)
AVDD: C12.1 C13.1 CT2.1 L2.2 L5.1 U4.120(AVDD) VREF1.1
AVSS: C12.2 C13.2 C14.2 C15.1 CT2.2 L4.2 U4.122(AVSS)
GND: C1.1 C2.1 C3.1 C4.1 C5.1 C7.1 C8.1 C9.1 C11.2 C16.1 C17.2 C20.1 C21.1 C22.1 C23.1 C24.1 C25.2 C26.2 C32.1 C33.2 C36.1 C37.2 C38.2 C39.2 C42.2 C43.2 C49.2 C53.2 C54.2 C55.2 C56.2 C61.1 C_VLCD.1 CON3.2(GND) CT1.2 CT3.2 CT4.2 CT5.2 CT6.2 CT7.2 CT11.2 CT15.2 CT16.2 CT17.2 CT18.2 CT21.2 ICEC1.2 ICEC2.2 ICEC3.2 ICEC4.2 ICEC5.2 ICEC6.2 ICEC7.1 ICEC8.1 ICEC9.1 ICEC10.1 ICEC11.1 ICEC12.2 ICECT1.2 ICECT2.2 ICECT3.2 ICED3.1 ICEJ1.5 ICEJ2.4 ICEJ3.5(GND) ICEJ4.9 ICEL2.1 ICER1.2 ICER9.1 ICESW1.1 ICESW2.4(A4) ICEU1.6(PB.1) ICEU1.7(PB.0) ICEU1.22(VSS) ICEU1.45(HSUSB_VSS) ICEU1.49(VSS) ICEU1.59(AVSS) ICEU2.4(GND) ICEU3.4(GND) ICEU3.5(DIR) ICEU4.4(GND) ICEU4.5(DIR) ICEUP1.1(GND) ICEX1.2(GND) ICEX1.4(GND) J1.10 J2.5(GND) J2.6(Shield) J2.7(Shield) J2.8(Shield) J2.9(Shield) J10.1 J10.3 J10.4 J10.5 JP2.1 JP2.2 JP2.3 JP2.4 JP10.1 JP10.2 L4.1 LEDG1.2 LoRa_Power.2 MBUS1.8(GND) MBUS1.9(GND) NU1.6(VSS) NU1.7(VSS) NU4.7(VSS) NU5.6(GND) R19.2 R40.2 R43.1 R49.2 SW1.1 SW5.2(A2) SW8.4(B2) SW9.4(B2) SW10.1 U3.2(GND) U4.11(VSS) U4.39(VSS) U4.52(VSS) U4.75(VSS) U4.103(VSS) U4.112(VSS) U9.15(GND) U10.1(GND) U10.10(GND) U10.11(GND) U10.20(GND) U11.1(GND) U11.5(SDO) U11.7(GND) U13.2(GND) U14.5(GND) U15.2(GND) U21.1(GND) U22.1(GND) UP1.1(GND) UP2.1(GND)
VBAT: C32.2 C33.1 R17.2 U4.30(VBAT) VDDIO1.2
VDD_MCU: AMMETER.2 C3.2 C4.2 C11.1 C20.2 C21.2 C22.2 C23.2 CT1.1 CT5.1 L2.1 R15.1 R16.2 R17.1 U4.12(VDD) U4.40(VDD) U4.53(VDD) U4.76(VDD) U4.104(VDD) U4.114(VDD) VDDIO.1 VDDIO1.1
VDDIO: C16.2 C17.1 R15.2 U4.61(VDDIO) VDDIO.2
BUSY: ICEJ4.2 ICEU1.27(PA.3) ICEU1.56(PB.12)
CANH: CAN0.1 JP7.1 R44.2 U13.7(CANH)
CANL: CAN0.2 JP7.2 R44.1 U13.6(CANL)
DC5V_IN: C49.1 CT11.1 D3.2 D4.2 D5.2 Q7.2(SOURCE) Q8.2(SOURCE) R61.1 R62.1
DM: ICEJ2.2 ICEJ3.2(D-) ICER6.2
DP: ICEJ2.3 ICEJ3.3(D+) ICER7.2
ETMCK_MOSI: ICESW2.8(B1) ICEU1.30(PA.0) ICEU1.52(PC.14)
ETMD0_MISO: ICESW2.7(B2) ICEU1.29(PA.1) ICEU1.53(PB.15)
ETMD2_CK: ICEJ4.4 ICEU1.28(PA.2) ICEU1.55(PB.13)
GREEN: ICES3.2 ICEU1.63(PB.8)
HXT_I: ICEC11.2 ICEU1.16(PF.3) ICEX1.1(XIN)
HXT_O: ICEC10.2 ICEU1.17(PF.2) ICEX1.3(XOUT)
ICE5V: ICED1.2 ICEJPR1.4 ICEUP1.3(IN) ICEUP2.3(IN) L1.1
ICE_CLK: ICEJ1.3 ICER4.1 ICEU1.34(PF.1)
ICE_DAT: ICEJ1.2 ICER2.1 ICEU1.33(PF.0)
ICE_RST: ICEC9.2 ICEJ1.4 ICER3.2 ICEU1.32(nRESET)
ICELED: ICES0.2 ICEU1.15(PF.4)
ICEVCC: ICEJPR2.2 ICEL1.1
ICEVDD: ICEC4.1 ICEC5.1 ICEC7.2 ICEC8.2 ICECT2.1 ICEJ1.1 ICEL1.2 ICER2.2 ICER3.1 ICER4.2 ICER5.2 ICERP1.1(R1) ICERP1.3(R2) ICERP1.5(R3) ICERP1.7(R4) ICEU1.13(VBAT) ICEU1.23(VDD) ICEU1.31(VDDIO) ICEU1.51(VDD) ICEU1.57(AVDD) ICEU1.58(VREF) ICEU3.8(VCCB) ICEU4.8(VCCB)
ISPLED: ICES1.2 ICEU1.19(PC.6)
KEY1: ICER5.1 ICESW1.2 ICEU1.18(PC.7)
LCD_SEG3: JLCD_1.4 S2.10(B7)
LCD_SEG4: JLCD_1.5 S2.11(B6)
LCD_SEG5: JLCD_1.6 S2.12(B5)
LCD_SEG6: JLCD_1.7 S2.13(B4)
LCD_SEG7: JLCD_1.8 S2.14(B3)
LCD_SEG11: JLCD_1.12 S2.15(B2)
LCD_SEG12: JLCD_1.13 S2.16(B1)
LDO_CAP_1: C5.2 L14.2 U4.115(LDO_CAP)
LDO_CAP_2: C24.2 U4.54(LDO_CAP)
LoRa_VDD: C56.1 CT18.1 CT21.1 R20.1 R69.1 U10.12(VDD) U10.13(VDD) U15.1(IN) U22.2(OUT) U22.4(OUT)
MBUS_AN: MBUS1.1(AN) U4.124(PB.10)
MBUS_CLK: MBUS1.4(SCK) S1.11(B6)
MBUS_CS: MBUS1.3(CS) S1.10(B7)
MBUS_INT: MBUS1.15(INT) U4.86(PD.5/I2C1_SCL)
MBUS_MISO: MBUS1.5(MISO) S1.13(B4)
MBUS_MOSI: MBUS1.6(MOSI) S1.12(B5)
MBUS_PWM: MBUS1.16(PWM) S1.14(B3)
MBUS_RST: MBUS1.2(RST) U4.87(PD.4/I2C1_SDA)
MBUS_RX: MBUS1.14(RX) S1.15(B2)
MBUS_SCL: MBUS1.12(SCL) NU2.6(A5/SCL) U4.9(PB.1/NU2_A5)
MBUS_SDA: MBUS1.11(SDA) NU2.5(A4/SDA) U4.10(PB.0/NU2_A4)
MBUS_TX: MBUS1.13(TX) S1.16(B1)
MCU_RX: ICEJ4.10 ICESW2.2(A2) J1.9 U4.126(PB.8)
MCU_TX: ICEJ4.8 ICESW2.1(A1) J1.7 U4.125(PB.9)
MCUVCC: ICED4.1 ICEJPR1.2
MCUVCC_DIODE: AMMETER.1 C38.1 C39.1 C42.1 C43.1 ICED4.2 ICEJ4.1 J1.2 JP1.1 JP1.2 JP1.3 JP1.4 NU1.2(VDD) NU5.2(VCC) R3.1 R6.1 R7.1 R13.1 R14.1 R16.1 R18.1 R48.1 R64.1 R65.1 R68.1 SW2.3(B1) SW2.4(B2) U11.2(CSB) U11.6(VDDIO) U11.8(VDD) U13.3(VCC) U14.8(VCC)
MSG_EN: ICESW2.5(B4) ICEU1.12(PF.6)
NU1_3VCC: CT3.1 MBUS1.7(+3.3V) NU1.4(3VCC) SW2.2(A2) UP1.2(OUT) UP1.4(OUT)
NU1_5VCC: C25.1 CT6.1 D1.2 D2.2 D4.1 L1.2 MBUS1.10(+5V) NU1.5(5VCC) R12.1 U3.5(IN) UP1.3(IN)
NU1_VIN: CT4.1 NU1.8(VIN) UP2.3(IN)
P1: NU2.3(A2) U4.1(PB.5/NU2_A2)
P2: NU2.4(A3) U4.2(PB.4/NU2_A3)
P3: NU3.2(D1) U4.3(PB.3/NU3_D1/UART1_TXD)
P4: NU3.1(D0) U4.4(PB.2/NU3_D0/UART1_RXD)
P5: U4.5(PC.12/SPI3_MISO) U10.15(MISO)
P6: U4.6(PC.11/SPI3_MOSI) U10.16(MOSI)
P7: U4.7(PC.10/SPI3_CLK) U10.14(SCK)
P8: U4.8(PC.9/SPI3_SS) U10.17(NSS)
P13: NU5.3(USCI0_CLK) U4.13(PA.11/USCI0_CLK)
P14: NU5.4(USCI0_DAT0) U4.14(PA.10/USCI0_DAT0)
P15: NU5.1(USCI0_DAT1) U4.15(PA.9/USCI0_DAT1)
P16: U4.16(PA.8) U15.3(EN)
P17: NU5.7(USCI0_CTL0) U4.17(PC.13/USCI0_CTL0)
P18: U4.18(PD.12) U10.8(DIO5)
P19: U4.19(PD.11/CAN0_TXD) U13.1(D)
P20: U4.20(PD.10/CAN0_RXD) U13.4(R)
P21: JLCD_1.48 U4.21(PG.2/LCD_SEG39)
P22: JLCD_1.47 U4.22(PG.3/LCD_SEG38)
P23: JLCD_1.46 U4.23(PG.4/LCD_SEG37)
P24: U4.24(PF.11) U10.7(DIO4)
P25: U4.25(PF.10) U10.6(DIO3)
P26: U4.26(PF.9) U10.5(DIO2)
P27: U4.27(PF.8) U10.4(DIO1)
P28: U4.28(PF.7) U10.3(DIO0)
P29: U4.29(PF.6) U10.2(NRESET)
P31: R1.2 U4.31(PF.5/X32_IN)
P32: R4.2 U4.32(PF.4/X32_OUT)
P33: JLCD_1.45 U4.33(PH.4/LCD_SEG36)
P34: JLCD_1.44 U4.34(PH.5/LCD_SEG35)
P35: JLCD_1.43 U4.35(PH.6/LCD_SEG34)
P36: JLCD_1.42 U4.36(PH.7/LCD_SEG33)
P37: R2.2 U4.37(PF.3/XT1_IN)
P38: R5.2 U4.38(PF.2/XT1_OUT)
P41: JLCD_1.41 U4.41(PE.8/LCD_SEG32)
P42: JLCD_1.40 U4.42(PE.9/LCD_SEG31)
P43: JLCD_1.39 U4.43(PE.10/LCD_SEG30)
P44: C61.2 R68.2 SW10.2 U4.44(PE.11)
P45: R37.2 U4.45(PE.12) U9.1(RST)
P46: U4.46(PE.13/UART4_nRTS) U9.7(IO13)
P47: R40.1 U4.47(PC.8/UART4_nCTS) U9.16(IO15)
P48: U4.48(PC.7/UART4_TXD) U9.21(RXD)
P49: U4.49(PC.6/UART4_RXD) U9.22(TXD)
P50: NU3.7(D6) U4.50(PA.7/EPWM1_CH4)
P51: NU3.8(D7) U4.51(PA.6/EPWM1_CH5)
P55: JLCD_1.38 NU4.1(D8) U4.55(PA.5/EPWM0_CH0/LCD_SEG29)
P56: JLCD_1.37 NU4.2(D9) U4.56(PA.4/EPWM0_CH1/LCD_SEG28)
P57: JLCD_1.36 NU4.3(D10) U4.57(PA.3/SPI0_SS/LCD_SEG27)
P58: JLCD_1.35 NU4.6(D13) U4.58(PA.2/SPI0_CLK/LCD_SEG26)
P59: JLCD_1.34 NU4.5(D12) U4.59(PA.1/SPI0_MISO/LCD_SEG25)
P60: JLCD_1.33 NU4.4(D11) U4.60(PA.0/SPI0_MOSI/LCD_SEG24)
P62: JLCD_1.32 U4.62(PE.14/LCD_SEG23)
P63: JLCD_1.31 U4.63(PE.15/LCD_SEG22)
P64: C9.2 ICEJ4.7 ICEU1.14(PF.5) J1.8 NU1.3(MCU_RESET) NU5.5(RESET) R3.2 SW1.2 U4.64(nRESET)
P65: ICEJ4.3 ICEU1.10(PA.9) J1.4 R13.2 U4.65(PF.0/ICE_DAT)
P66: ICEJ4.5 ICEU1.9(PA.10) J1.6 R14.2 U4.66(PF.1/ICE_CLK)
P67: JLCD_1.24 U4.67(PD.9/LCD_COM7)
P68: JLCD_1.23 U4.68(PD.8/LCD_COM6)
P69: JLCD_1.22 NU3.4(D3) U4.69(PC.5/LCD_COM5)
P70: JLCD_1.21 NU3.3(D2) U4.70(PC.4/LCD_COM4)
P71: JLCD_1.20 NU3.5(D4) U4.71(PC.3/LCD_COM3)
P72: JLCD_1.19 NU3.6(D5) U4.72(PC.2/LCD_COM2)
P73: JLCD_1.18 NU4.10(I2C_SCL) U4.73(PC.1/LCD_COM1)
P74: JLCD_1.17 NU4.9(I2C_SDA) U4.74(PC.0/LCD_COM0)
P77: JLCD_1.30 U4.77(PG.9/LCD_SEG21)
P78: JLCD_1.29 U4.78(PG.10/LCD_SEG20)
P79: JLCD_1.28 U4.79(PG.11/LCD_SEG19)
P80: JLCD_1.27 U4.80(PG.12/LCD_SEG18)
P81: JLCD_1.26 U4.81(PG.13/LCD_SEG17)
P82: JLCD_1.25 U4.82(PG.14/LCD_SEG16)
P83: JLCD_1.16 U4.83(PG.15/LCD_SEG15)
P84: JLCD_1.15 U4.84(PD.7/LCD_SEG14)
P85: JLCD_1.14 U4.85(PD.6/LCD_SEG13)
P88: R49.1 U4.88(PD.3/USCI0_CLT1) U14.2(\\\\RE) U14.3(DE)
P89: U4.89(PD.2/USCI0_DAT1) U14.4(DI)
P90: R48.2 U4.90(PD.1/USCI0_DAT0) U14.1(RO)
P91: LEDR1.2 U4.91(PD.0)
P92: C_VLCD.2 U4.92(VLCD)
P94: R10.1 U4.94(PA.13/USB_D-)
P95: R11.1 U4.95(PA.14/USB_D+)
P96: J2.4(ID) U4.96(PA.15/USB_OTG_ID)
P97: S1.1(A1) S2.1(A1) U4.97(PE.7/LCD_SEG12)
P98: S1.2(A2) S2.2(A2) U4.98(PE.6/LCD_SEG11)
P99: JLCD_1.11 U4.99(PE.5/LCD_SEG10)
P100: JLCD_1.10 U4.100(PE.4/LCD_SEG9)
P101: JLCD_1.9 U4.101(PE.3/LCD_SEG8)
P102: S1.3(A3) S2.3(A3) U4.102(PE.2/LCD_SEG7)
P105: S1.4(A4) S2.4(A4) U4.105(PE.1/LCD_SEG6)
P106: S1.5(A5) S2.5(A5) U4.106(PE.0/LCD_SEG5)
P107: S1.6(A6) S2.6(A6) U4.107(PH.8/LCD_SEG5)
P108: S1.7(A7) S2.7(A7) U4.108(PH.9/LCD_SEG3)
P109: JLCD_1.3 U4.109(PH.10/LCD_SEG2)
P110: JLCD_1.2 U4.110(PH.11/LCD_SEG1)
P111: JLCD_1.1 U4.111(PD.14/LCD_SEG0)
P113: L14.1 U4.113(Vsw)
P116: R19.1 U3.4(EN/EN#) U4.116(PB.15/USB_VBUS_EN)
P117: R18.2 U3.3(OC#) U4.117(PB.14/USB_VBUS_ST)
P118: R65.2 U4.118(PB.13/UART0_TXD) U11.4(SCK)
P119: R64.2 U4.119(PB.12/UART0_RXD) U11.3(SDI)
P123: NU5.8(GPIO) U4.123(PB.11/NU5_GPIO)
P127: NU2.1(A0) U4.127(PB.7/NU2_A0/EADC0_CH7)
P128: NU2.2(A1) U4.128(PB.6/NU2_A1/EADC0_CH6)
RED: ICES2.2 ICEU1.62(PB.9)
RS485_A: JP8.1 R47.1 R50.2 RS485.1
RS485_B: JP8.2 R46.1 R50.1 RS485.2
SPIM_CLK: ICEU1.38(PC.2) ICEU4.7(B1)
SPIM_CLK_LV: ICEU2.6(CLK) ICEU4.2(A1)
SPIM_CS: ICEU1.37(PC.3) ICEU3.7(B1)
SPIM_CS_LV: ICEU2.1(CS#) ICEU3.2(A1)
SPIM_MISO0: ICEU1.39(PC.1) ICEU2.2(DO)
SPIM_MOSI0: ICEU1.40(PC.0) ICEU4.6(B2)
SPIM_MOSI0_LV: ICEU2.5(DI) ICEU4.3(A2)
SWO: ICEJ4.6 ICEU1.26(PA.4)
USB_HS_CAP: ICEC2.1 ICEU1.47(HSUSB_VDD12_CAP)
USB_HS_D+: ICER7.1 ICEU1.46(HSUSB_D+)
USB_HS_D-: ICER6.1 ICEU1.44(HSUSB_D-)
USB_HS_REXT: ICER1.1 ICEU1.41(HSUSB_VRES)
USB_HS_VBUS: ICED1.1 ICED3.2 ICEJ2.1 ICEJ3.1(VBUS) ICEU1.43(HSUSB_VBUS)
USB_VBUS: C26.1 CT7.1 D1.1 J2.1(VBUS) U3.1(OUT) U4.93(PA.12/USB_VBUS)
VREF: C14.1 C15.2 L5.2 NU4.8(VREF) U4.121(VREF) VREF1.2
WiFi_IO0: R41.2 SW5.3(B1) U9.18(IO0)
WiFi_VDD: C37.1 C54.1 CT16.1 R37.1 R38.1 R39.1 R41.1 U9.8(VCC) U21.2(OUT) U21.4(OUT)
N16825237: LEDG1.1 R6.2
N16825240: LEDR1.1 R7.2
N16840819: ICEC6.1 ICEU1.24(LDO_CAP)
N16840960: ICEC3.1 ICEU1.50(LDO_CAP)
N17019924: ICER8.2 ICER9.2 ICEUP2.1(ADJ)
N17029977: ICERP1.8(R4) ICES3.1
N17029979: ICERP1.6(R3) ICES2.1
N17030004: ICERP1.4(R2) ICES1.1
N17030010: ICERP1.2(R1) ICES0.1
N17042369: ICEJ3.6(Shield) ICEJ3.7(Shield) ICEJ3.8(Shield) ICEJ3.9(Shield) ICEJ3.10(Shield) ICEJ3.11(Shield) ICEL2.2
N17125028: R12.2 SW2.1(A1)
N17155328: ICER18.1 ICEU2.7(HOLD#)
N17155343: ICER19.1 ICEU2.3(WP#)
N17159369: C8.2 R5.1 X1.1
N17159371: C2.2 R2.1 X1.2
N17159463: C1.2 R1.1 X2.1
N17159465: C7.2 R4.1 X2.2
N17167442: D2.1 UP2.2(OUT) UP2.4(OUT)
N17266794: J2.3(D+) R11.2
N17266796: J2.2(D-) R10.2
N17342127: R38.2 U9.17(IO2)
N17342152: R39.2 U9.3(EN)
N17347231: R43.2 U13.8(Rs)
N17348081: R46.2 U14.7(B)
N17348113: R47.2 U14.6(A)
N17378458: CON3.1(V-IN) D3.1
N17382829: Q7.1(GATE) R61.2 SW8.1(A1)
N17382845: C53.1 CT15.1 Q7.3(DRAIN) U21.3(IN)
N17383381: Q8.1(GATE) R62.2 SW9.1(A1)
N17383395: C55.1 CT17.1 Q8.3(DRAIN) U22.3(IN)
N17394409: D5.1 JP9.1 JP9.2
N17419503: LoRa_Power.1 R69.2
N17434495: C36.2 R20.2 U10.9(TCXO_VDD) U15.5(OUT)
N17434553: J10.2 U10.19(RF)

Not connected (* = marked no-connect by the designer): H1 1; H2 1; H3 1; H4 1; ICEJ3 4(ID)*; ICESW2 3(A3)* 6(B3)*; ICEU1 1(PB.6)* 2(PB.5)* 3(PB.4)* 4(PB.3)* 5(PB.2)* 8(PA.11)* 11(PA.8)* 20(PA.7)* 21(PA.6)* 25(PA.5)* 35(PC.5) 36(PC.4) 48(HSUSB_ID)* 54(PB.14)* 60(PB.11)* 61(PB.10)* 64(PB.7)*; ICEU3 3(A2)* 6(B2)*; J1 1* 3* 5*; NU1 1(NC)*; S1 8(A8) 9(B8); S2 8(A8) 9(B8); SW5 1(A1)* 4(B2)*; SW8 2(A2)* 3(B1)*; SW9 2(A2)* 3(B1)*; U9 2(ADC)* 4(IO16)* 5(IO14)* 6(IO12)* 9(CS0)* 10(MISO)* 11(IO9)* 12(IO10)* 13(MOSI)* 14(SCLK)* 19(IO4)* 20(IO5)*; U10 18(FEM_CTX)*; U13 5(Vref)*; U15 4(NC)*

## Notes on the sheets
sheet 1
- Off-page Connector
- DEBUG
- RESET
- SPI FLASH
- Nu-Trace,   ID0 = 1, ID1 = 1
  Nu-Link2,   ID0 = 0, ID1 = 1
  Nu-LInk2-Me, ID0 = 0, ID1 = 0
- NULINK ID
- KEY
- Power Switch
- VCOM SWITCH
- 12M Crystal
- USB 2.0 HIGH SPEED DEVICES
- LED
- ICE INTERFACE
sheet 2
- P1 - P32
- P65 - P96
- Off-page Connector
- P33 - P64
- P97 - P128
- Bypass Cap
- LDO_CAP & VSW
- ICE
- RESET
- HXT & LXT Crystal
- Button
- Power
- LED
- Mounting Hole
- High Active
- OC# is Open-drain Pin
- USB1.1 OTG HOST/DEVICE
sheet 3
- UNO Interface
sheet 4
- Off-page Connector
- WiFi Module
- FW Update
sheet 5
- Off-page Connector
- LoRa Module only supports 1.8v ~ 3.6v voltage. This means
  VDD cannot be selected to 5V power.
- LED
sheet 6
- Off-page Connector
- Environment Sensor
- Slave Address: 0x76
- Pull-up Resistors
sheet 7
- Off-page Connector
- CAN Tranceiver
- CAN Connector
- RS485 Tranceiver
- RS485 Connector
sheet 8
- Off-page Connector
- MikroBUS Interface
sheet 9
- LCD Off-page
sheet 10
- Off-page Connector
- WiFi Power
- LoRa Power
- Power DC5V
